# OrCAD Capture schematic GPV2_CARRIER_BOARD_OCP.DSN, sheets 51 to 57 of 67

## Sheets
51 057 CPLD 1: size C
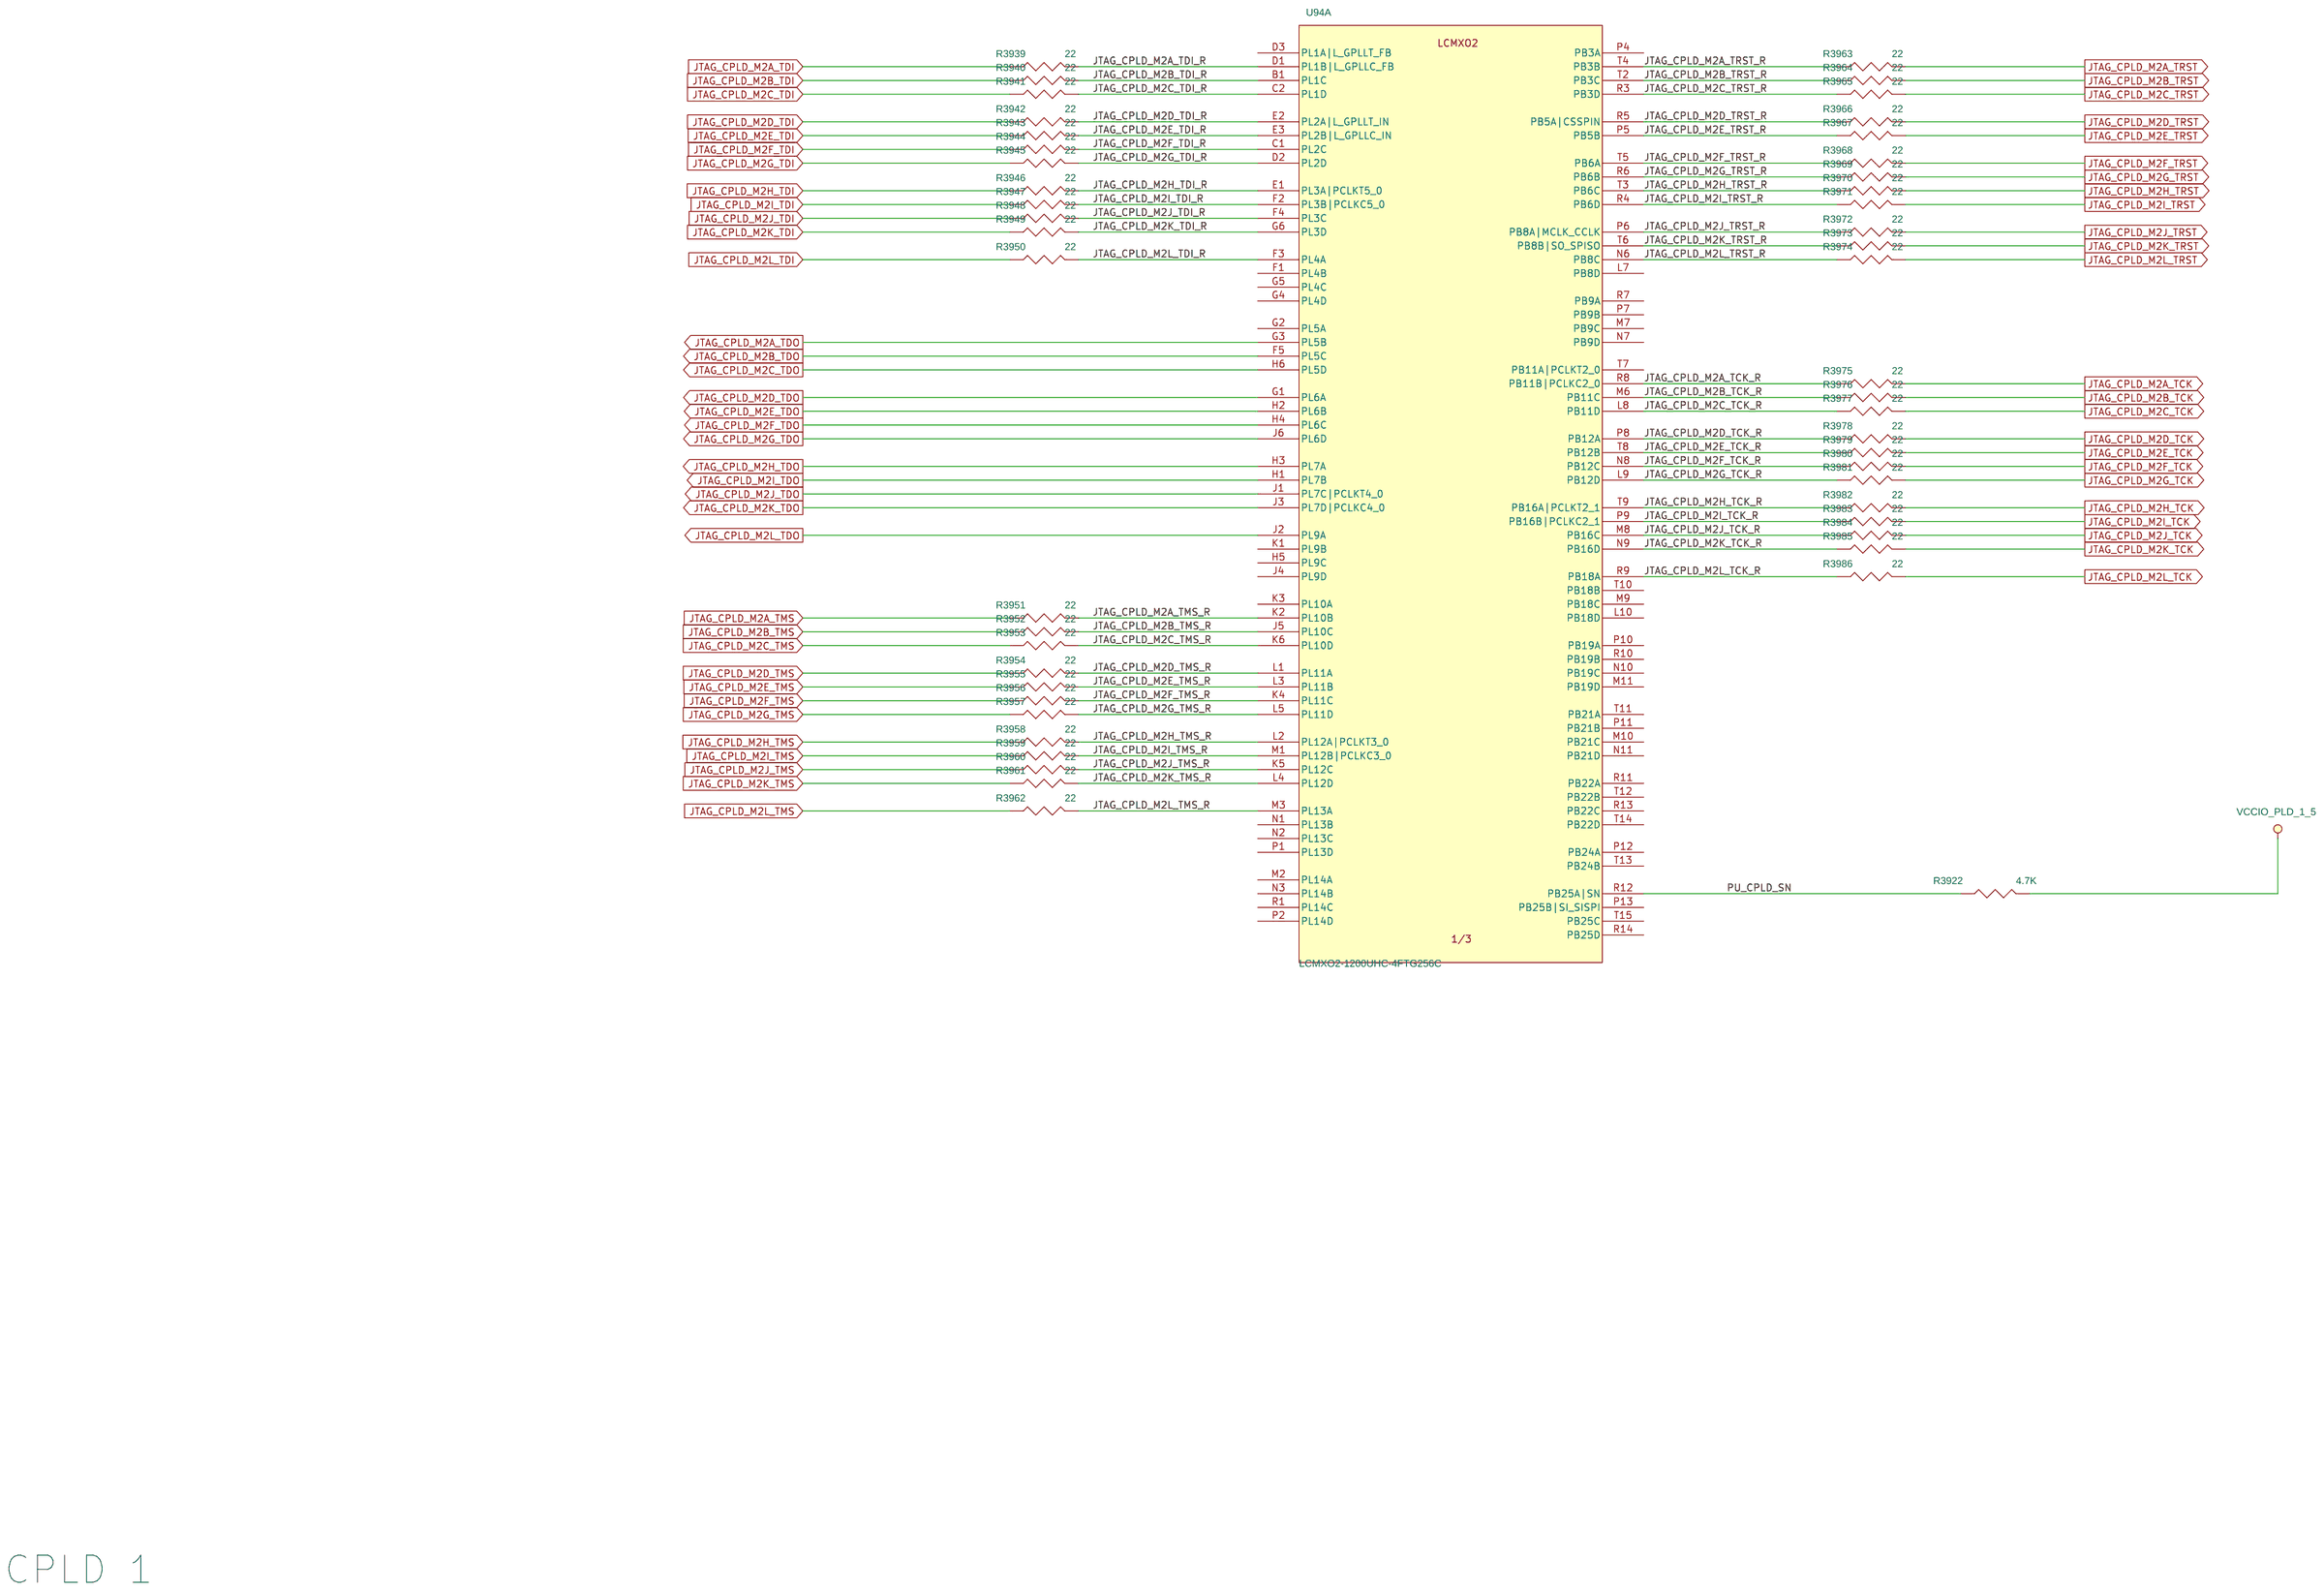
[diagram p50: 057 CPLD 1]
52 058 CPLD 2: size C
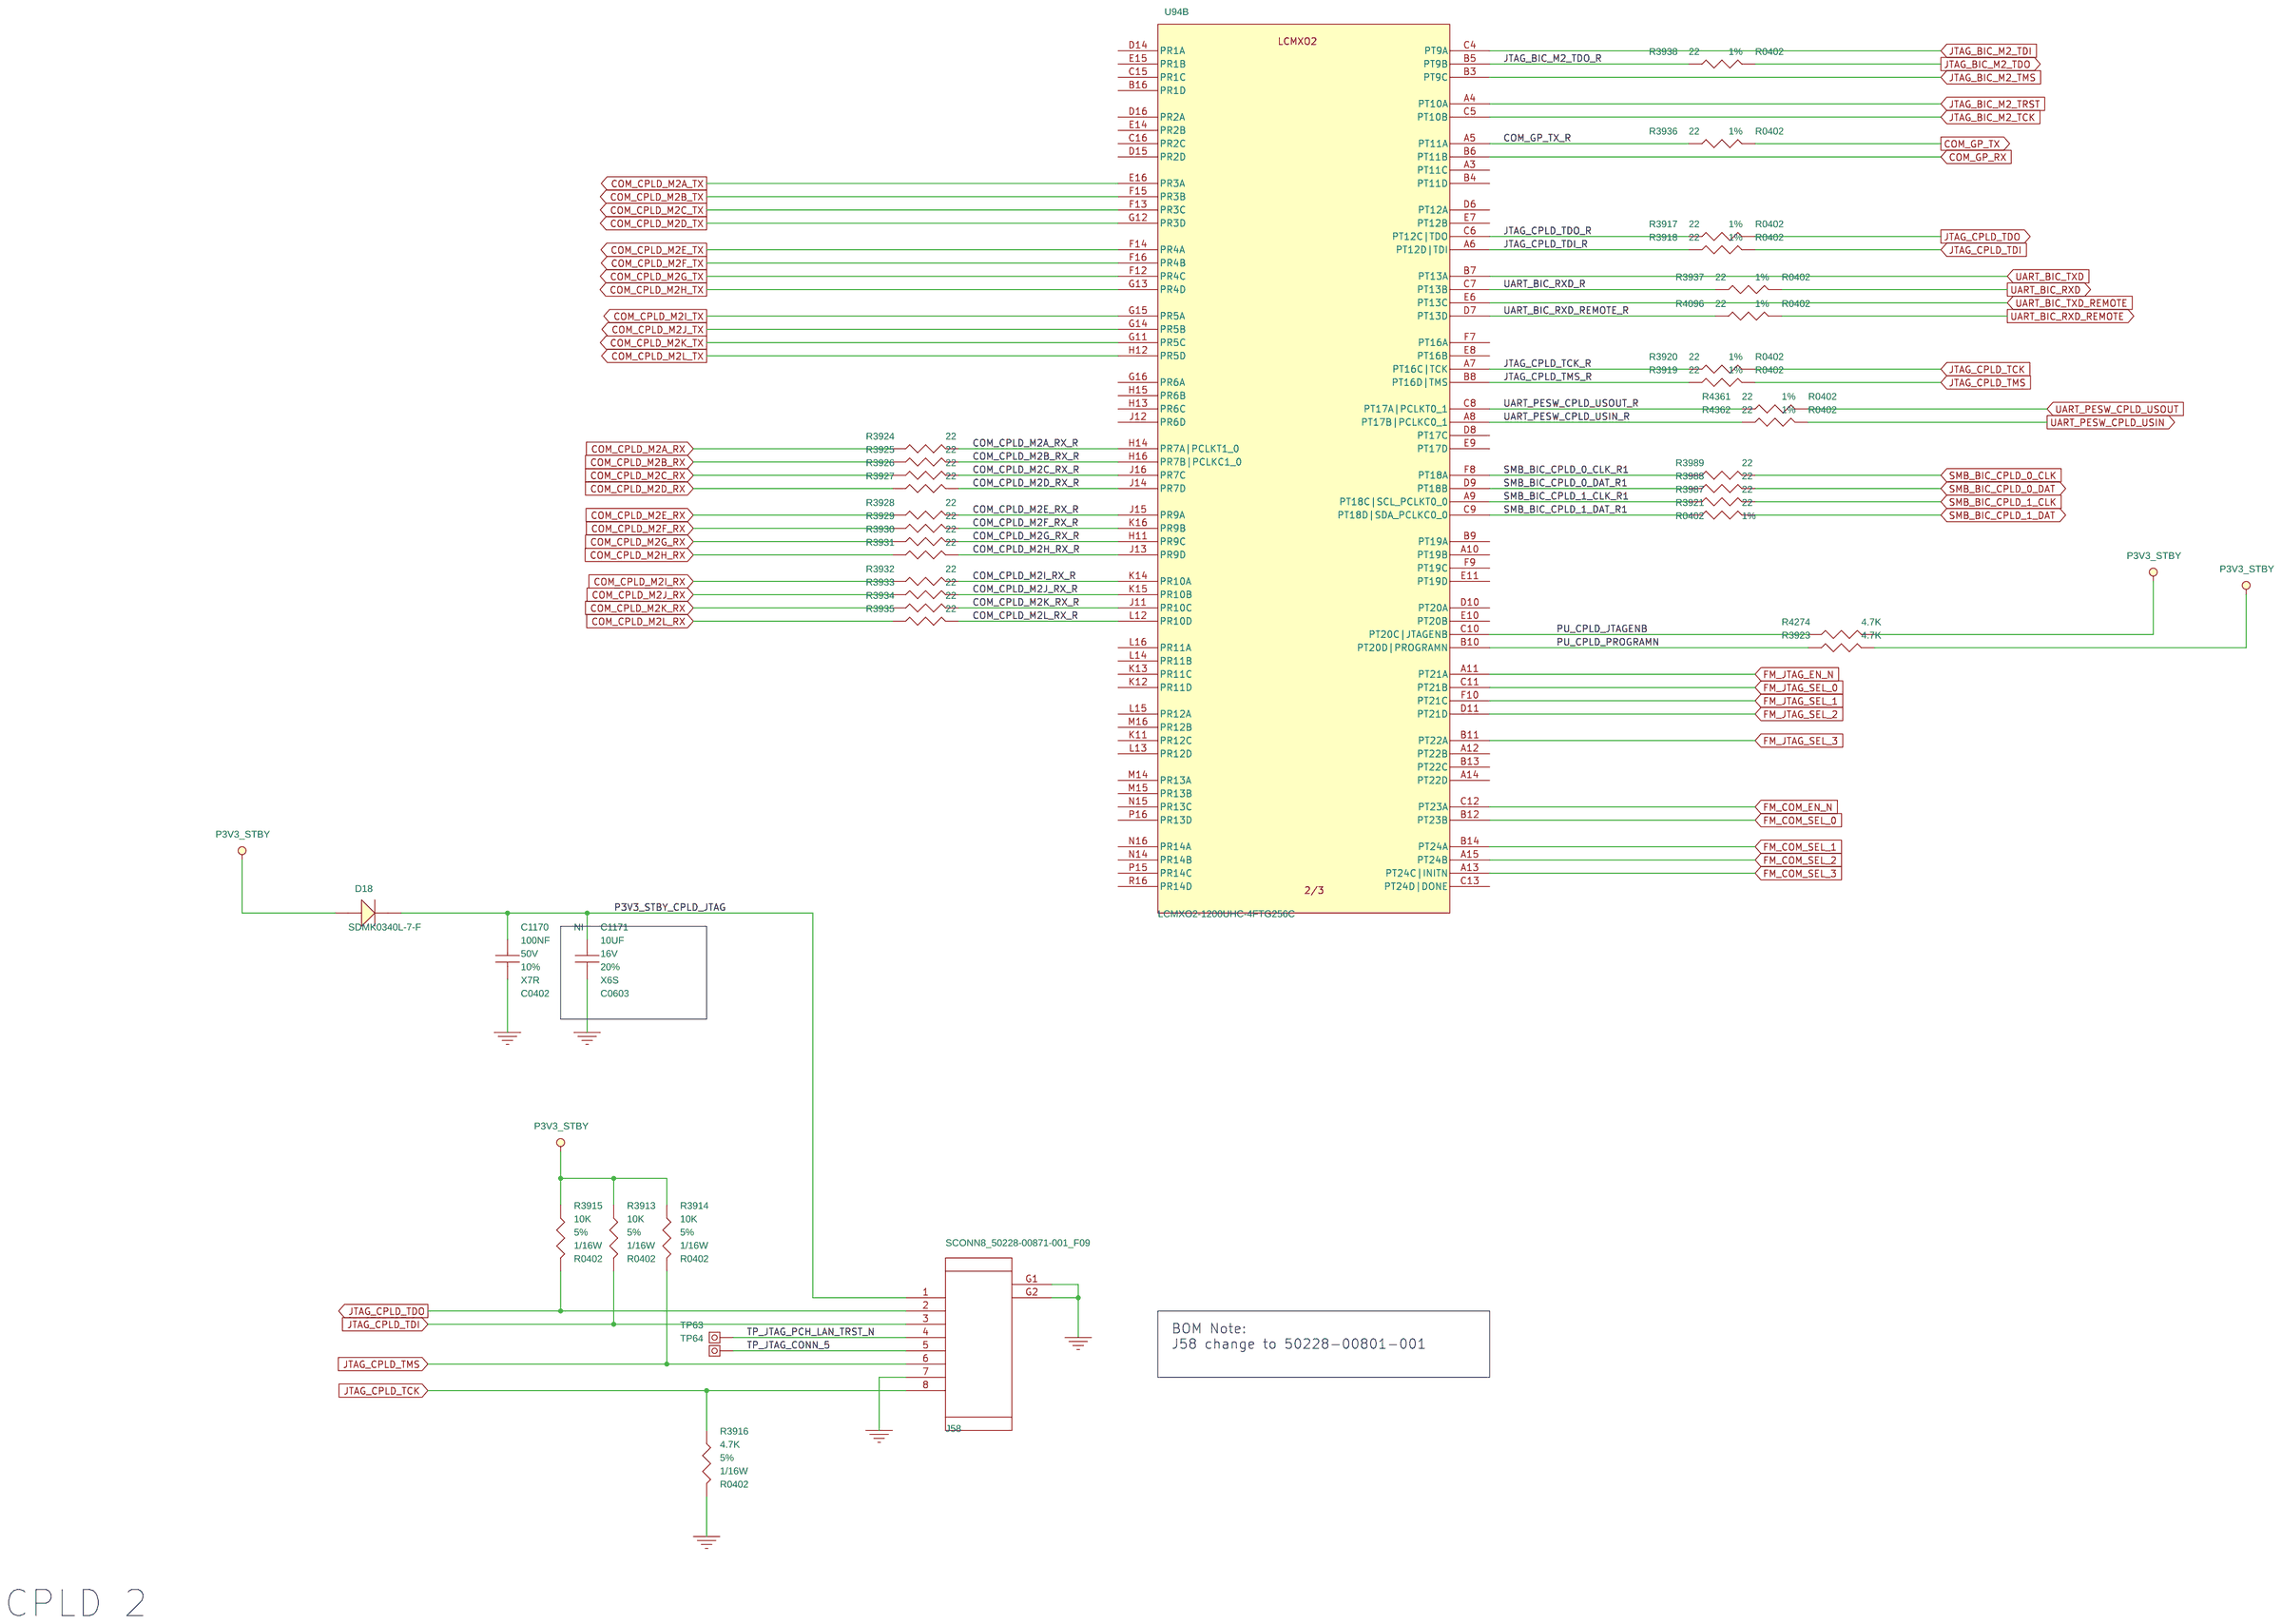
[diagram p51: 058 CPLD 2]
53 059 CPLD 3: size C
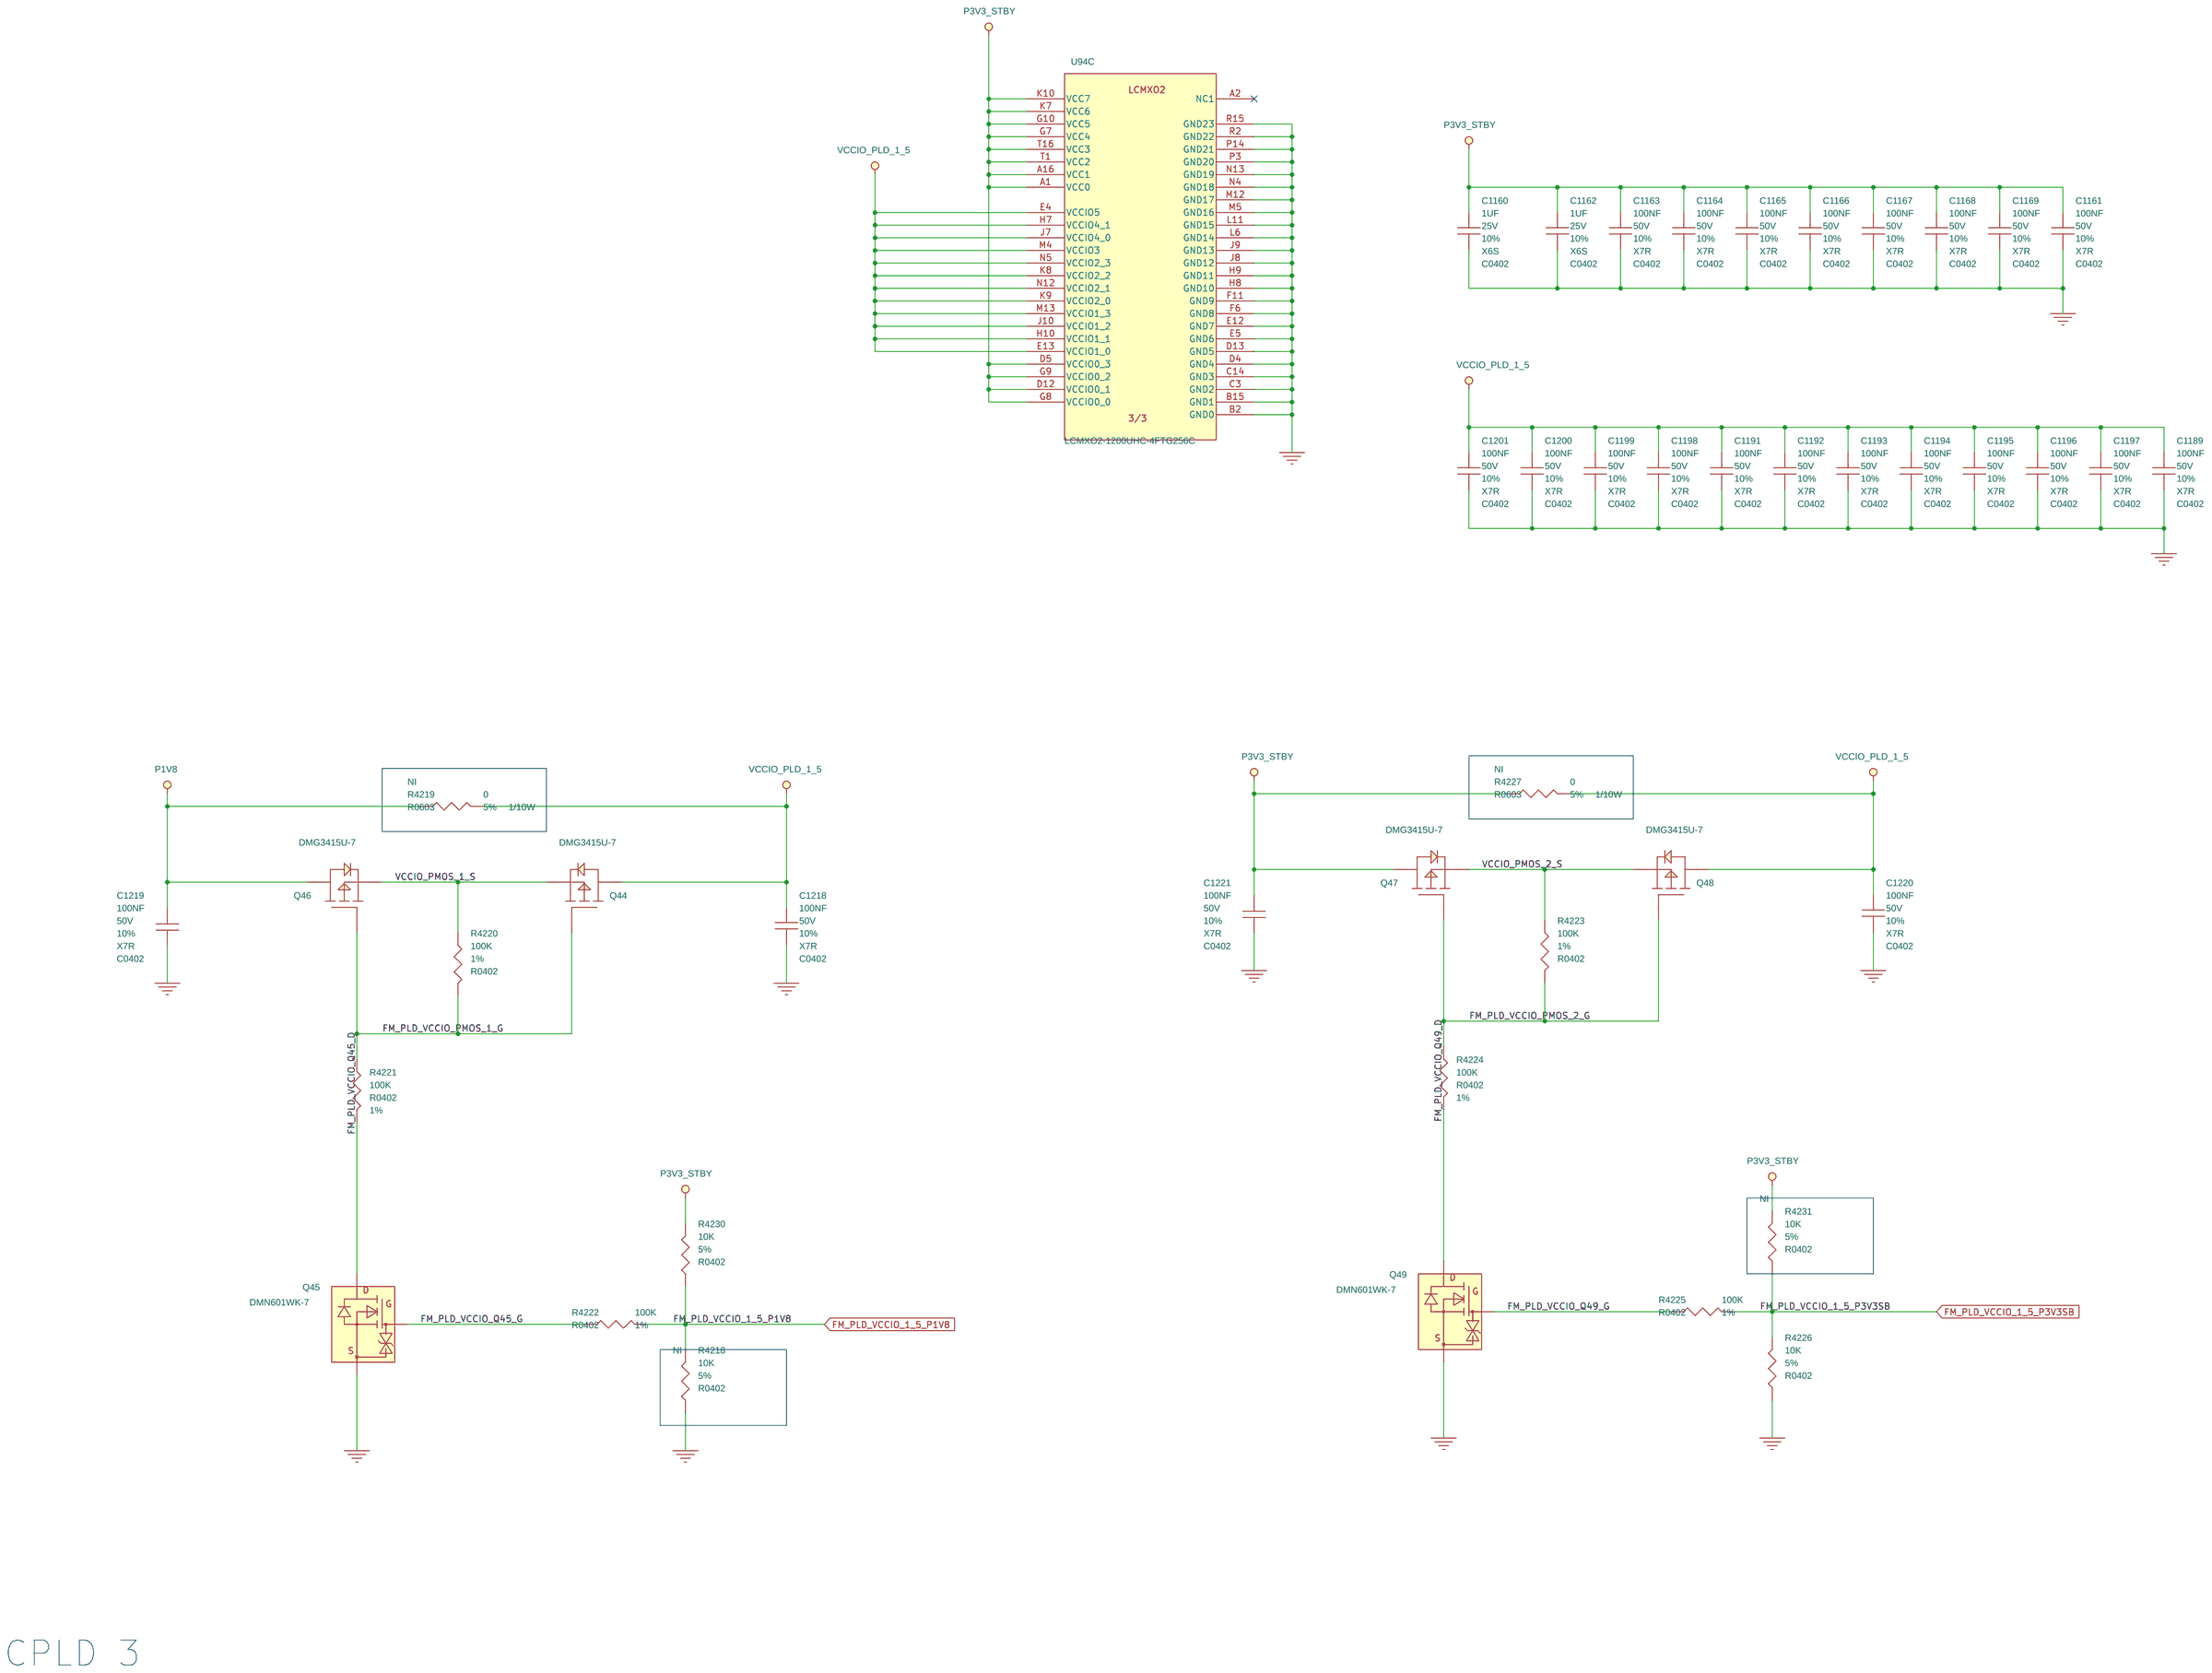
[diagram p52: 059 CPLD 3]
54 060 MISC 1: size C
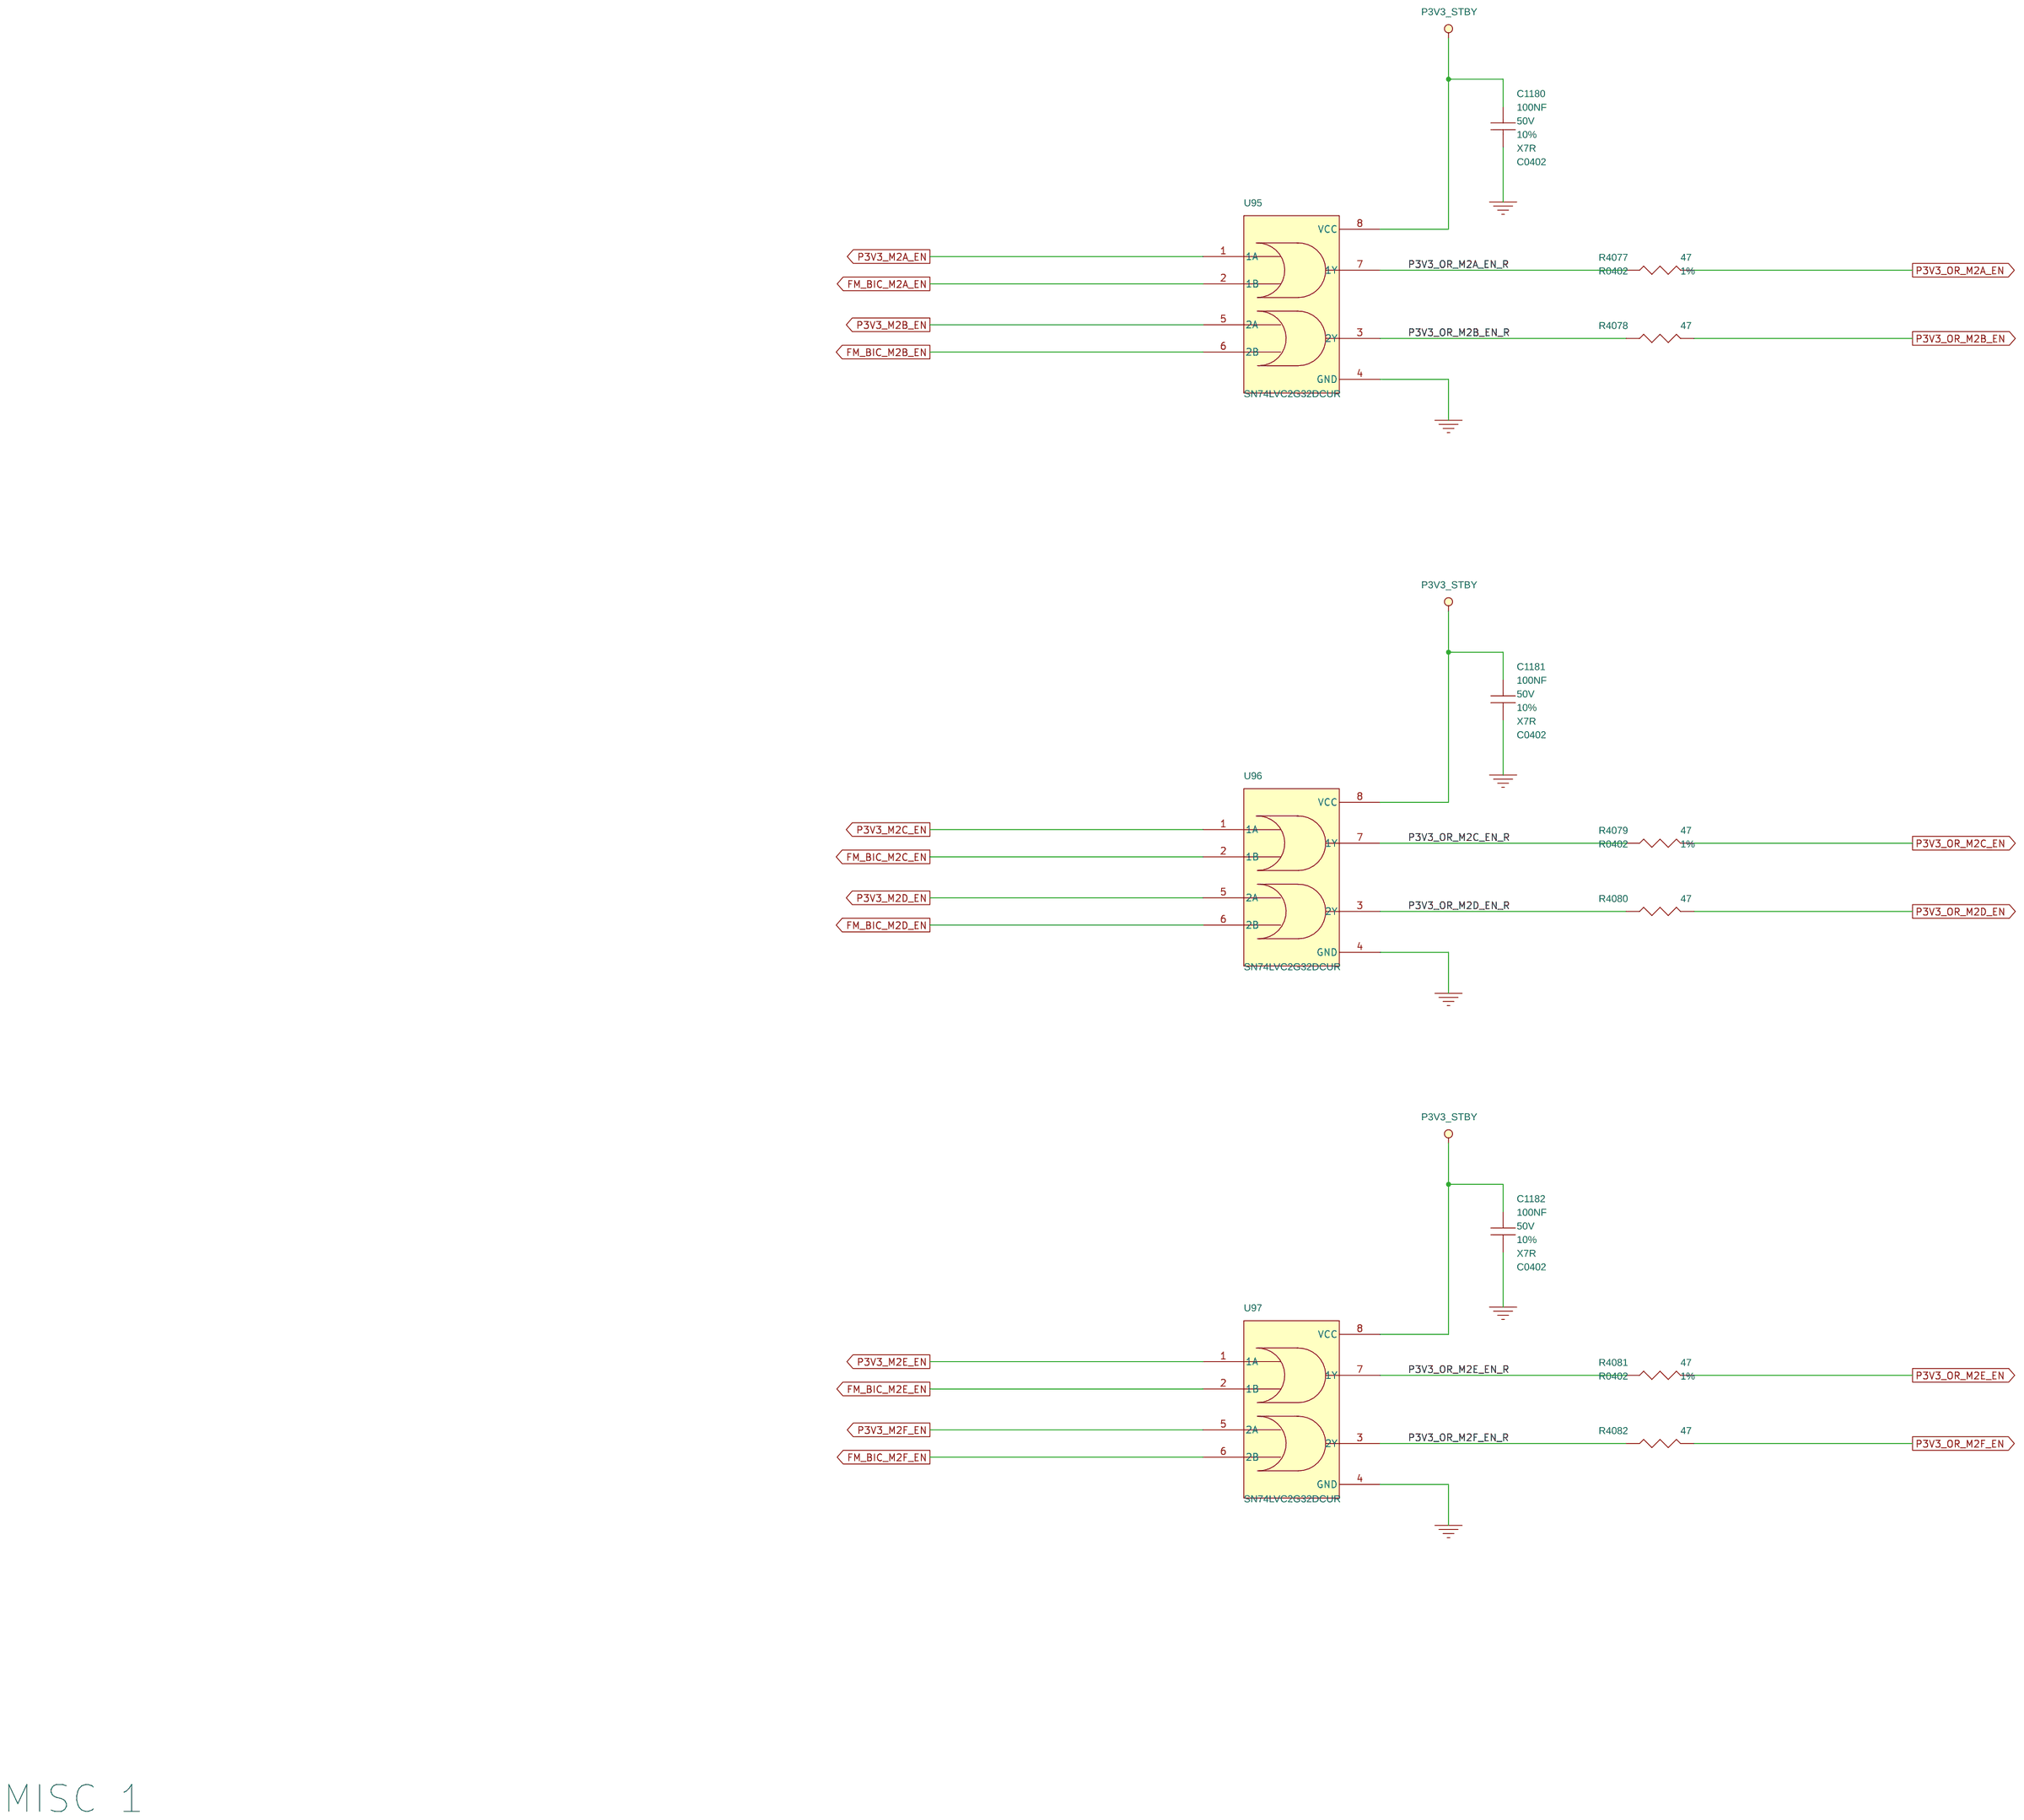
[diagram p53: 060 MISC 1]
55 061 MISC 2: size C
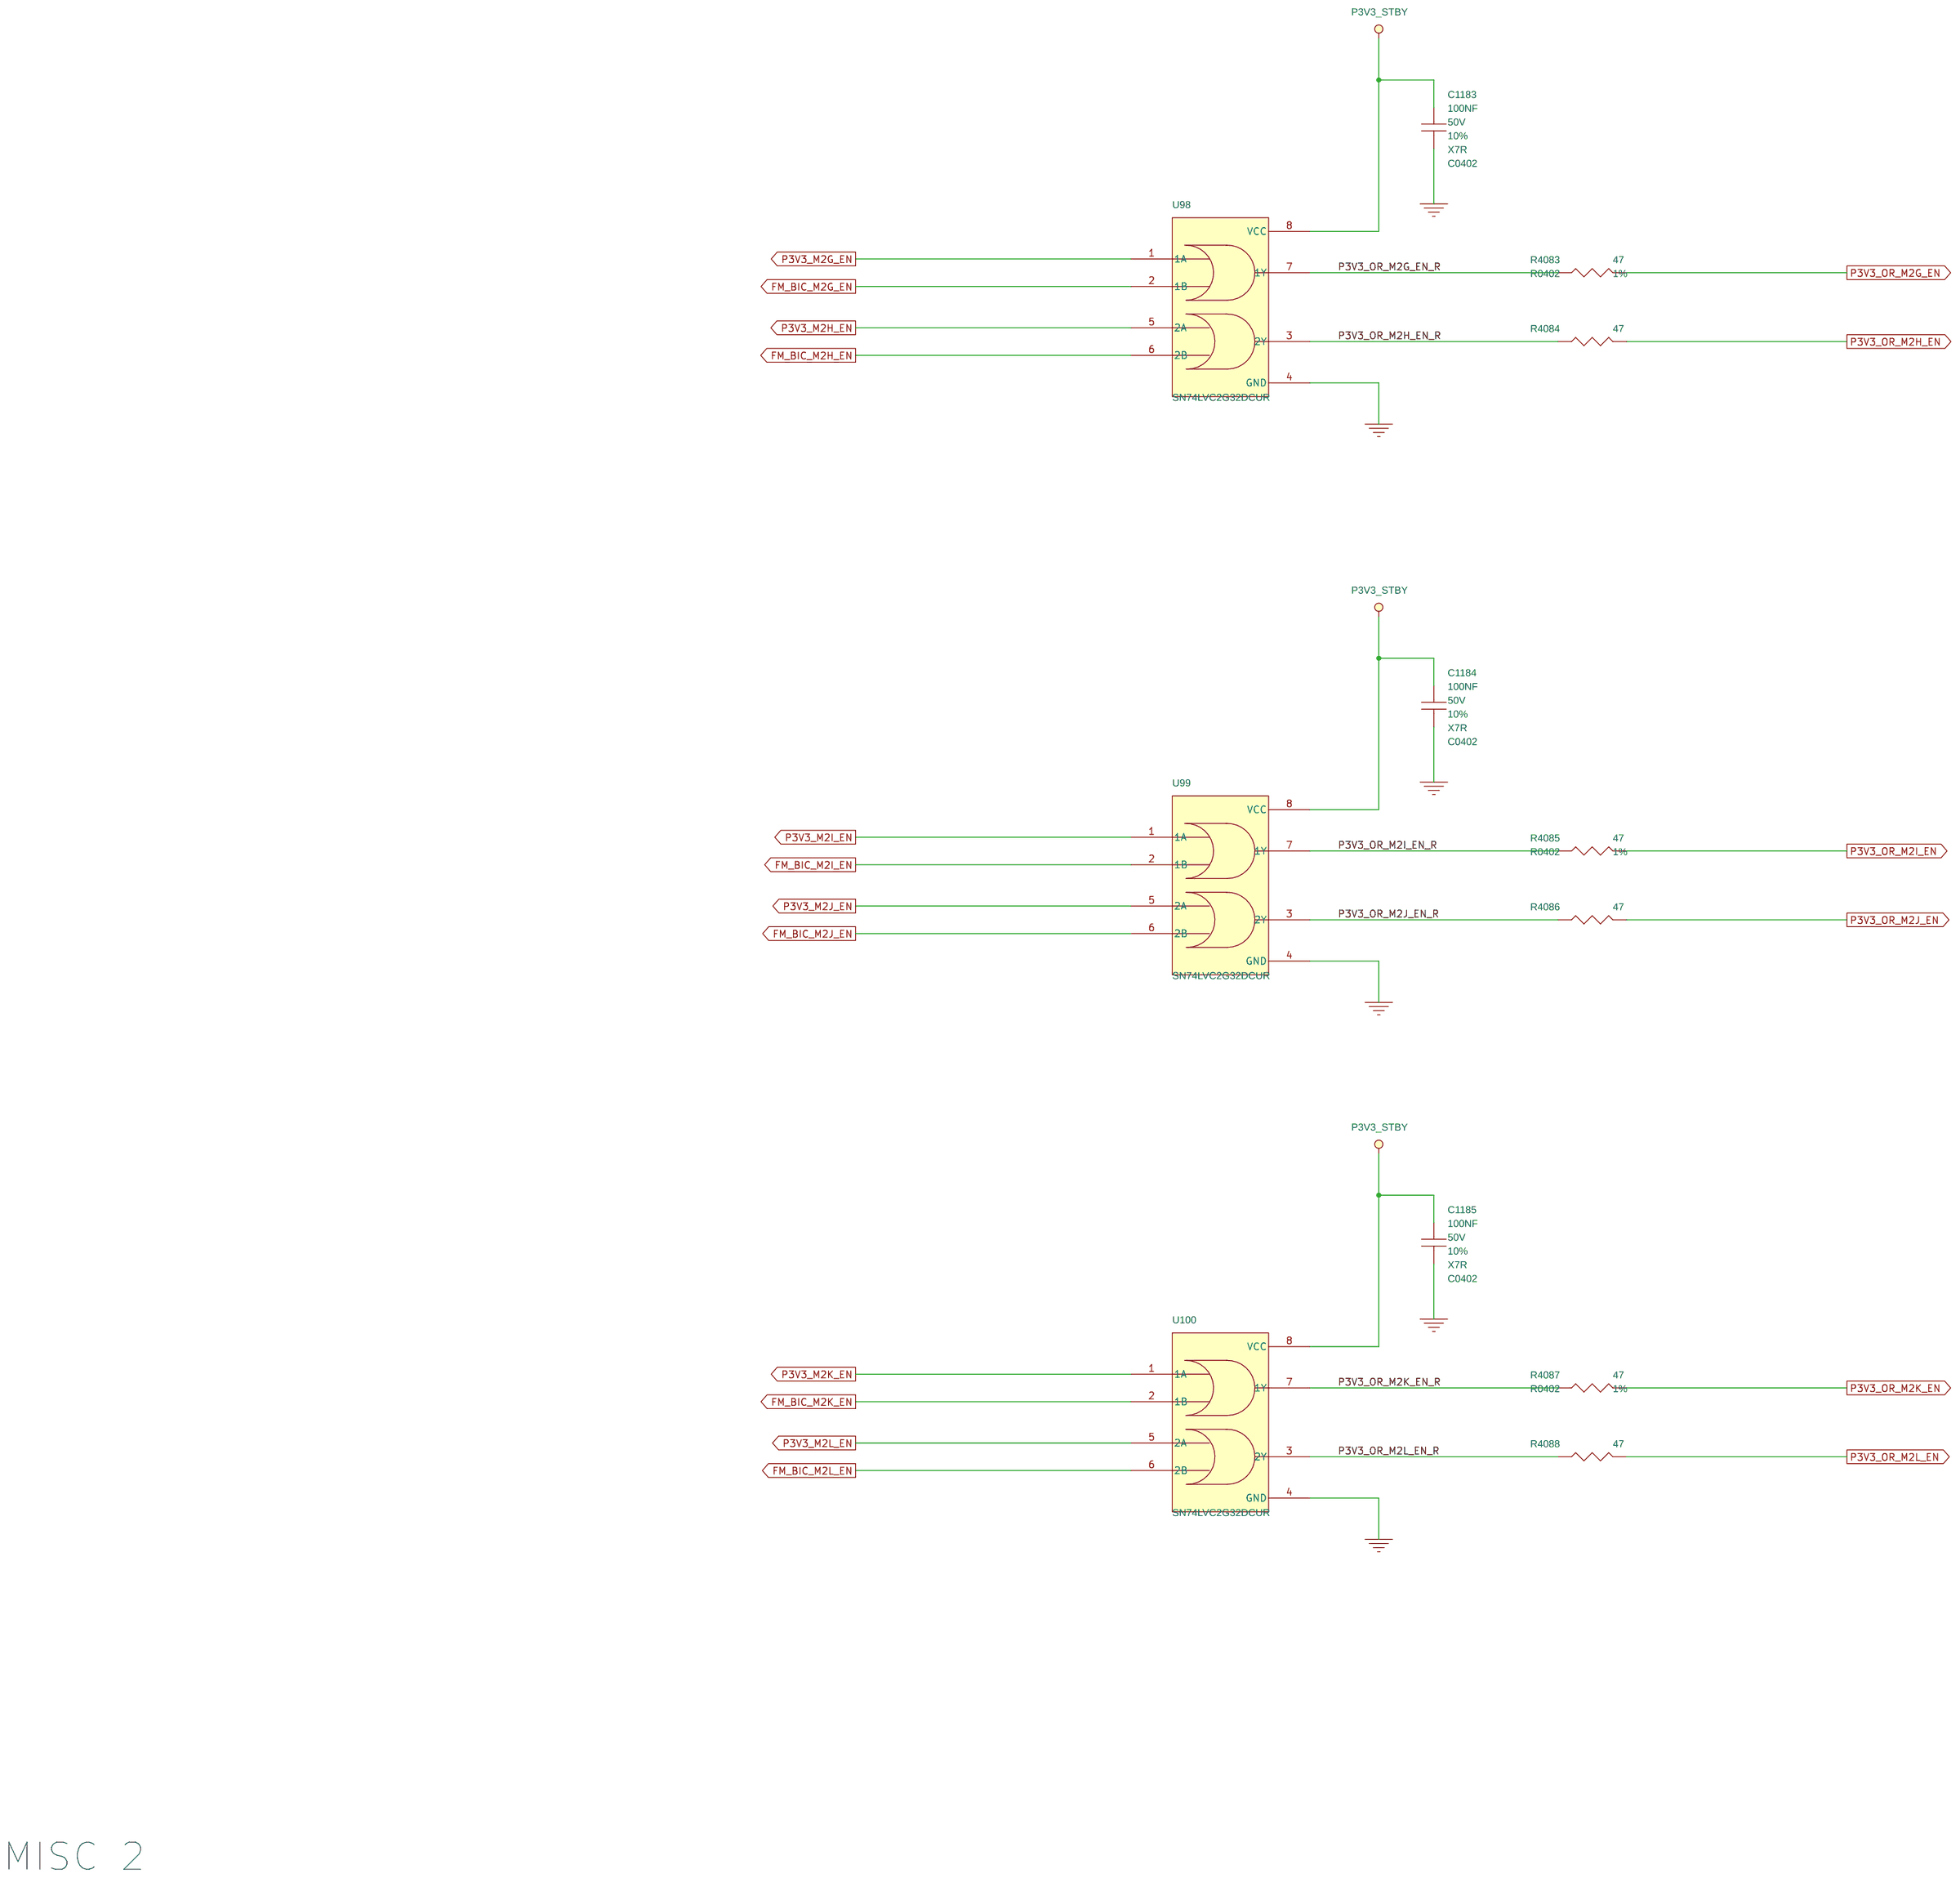
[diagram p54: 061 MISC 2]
56 062 P3V3_STBY: size C
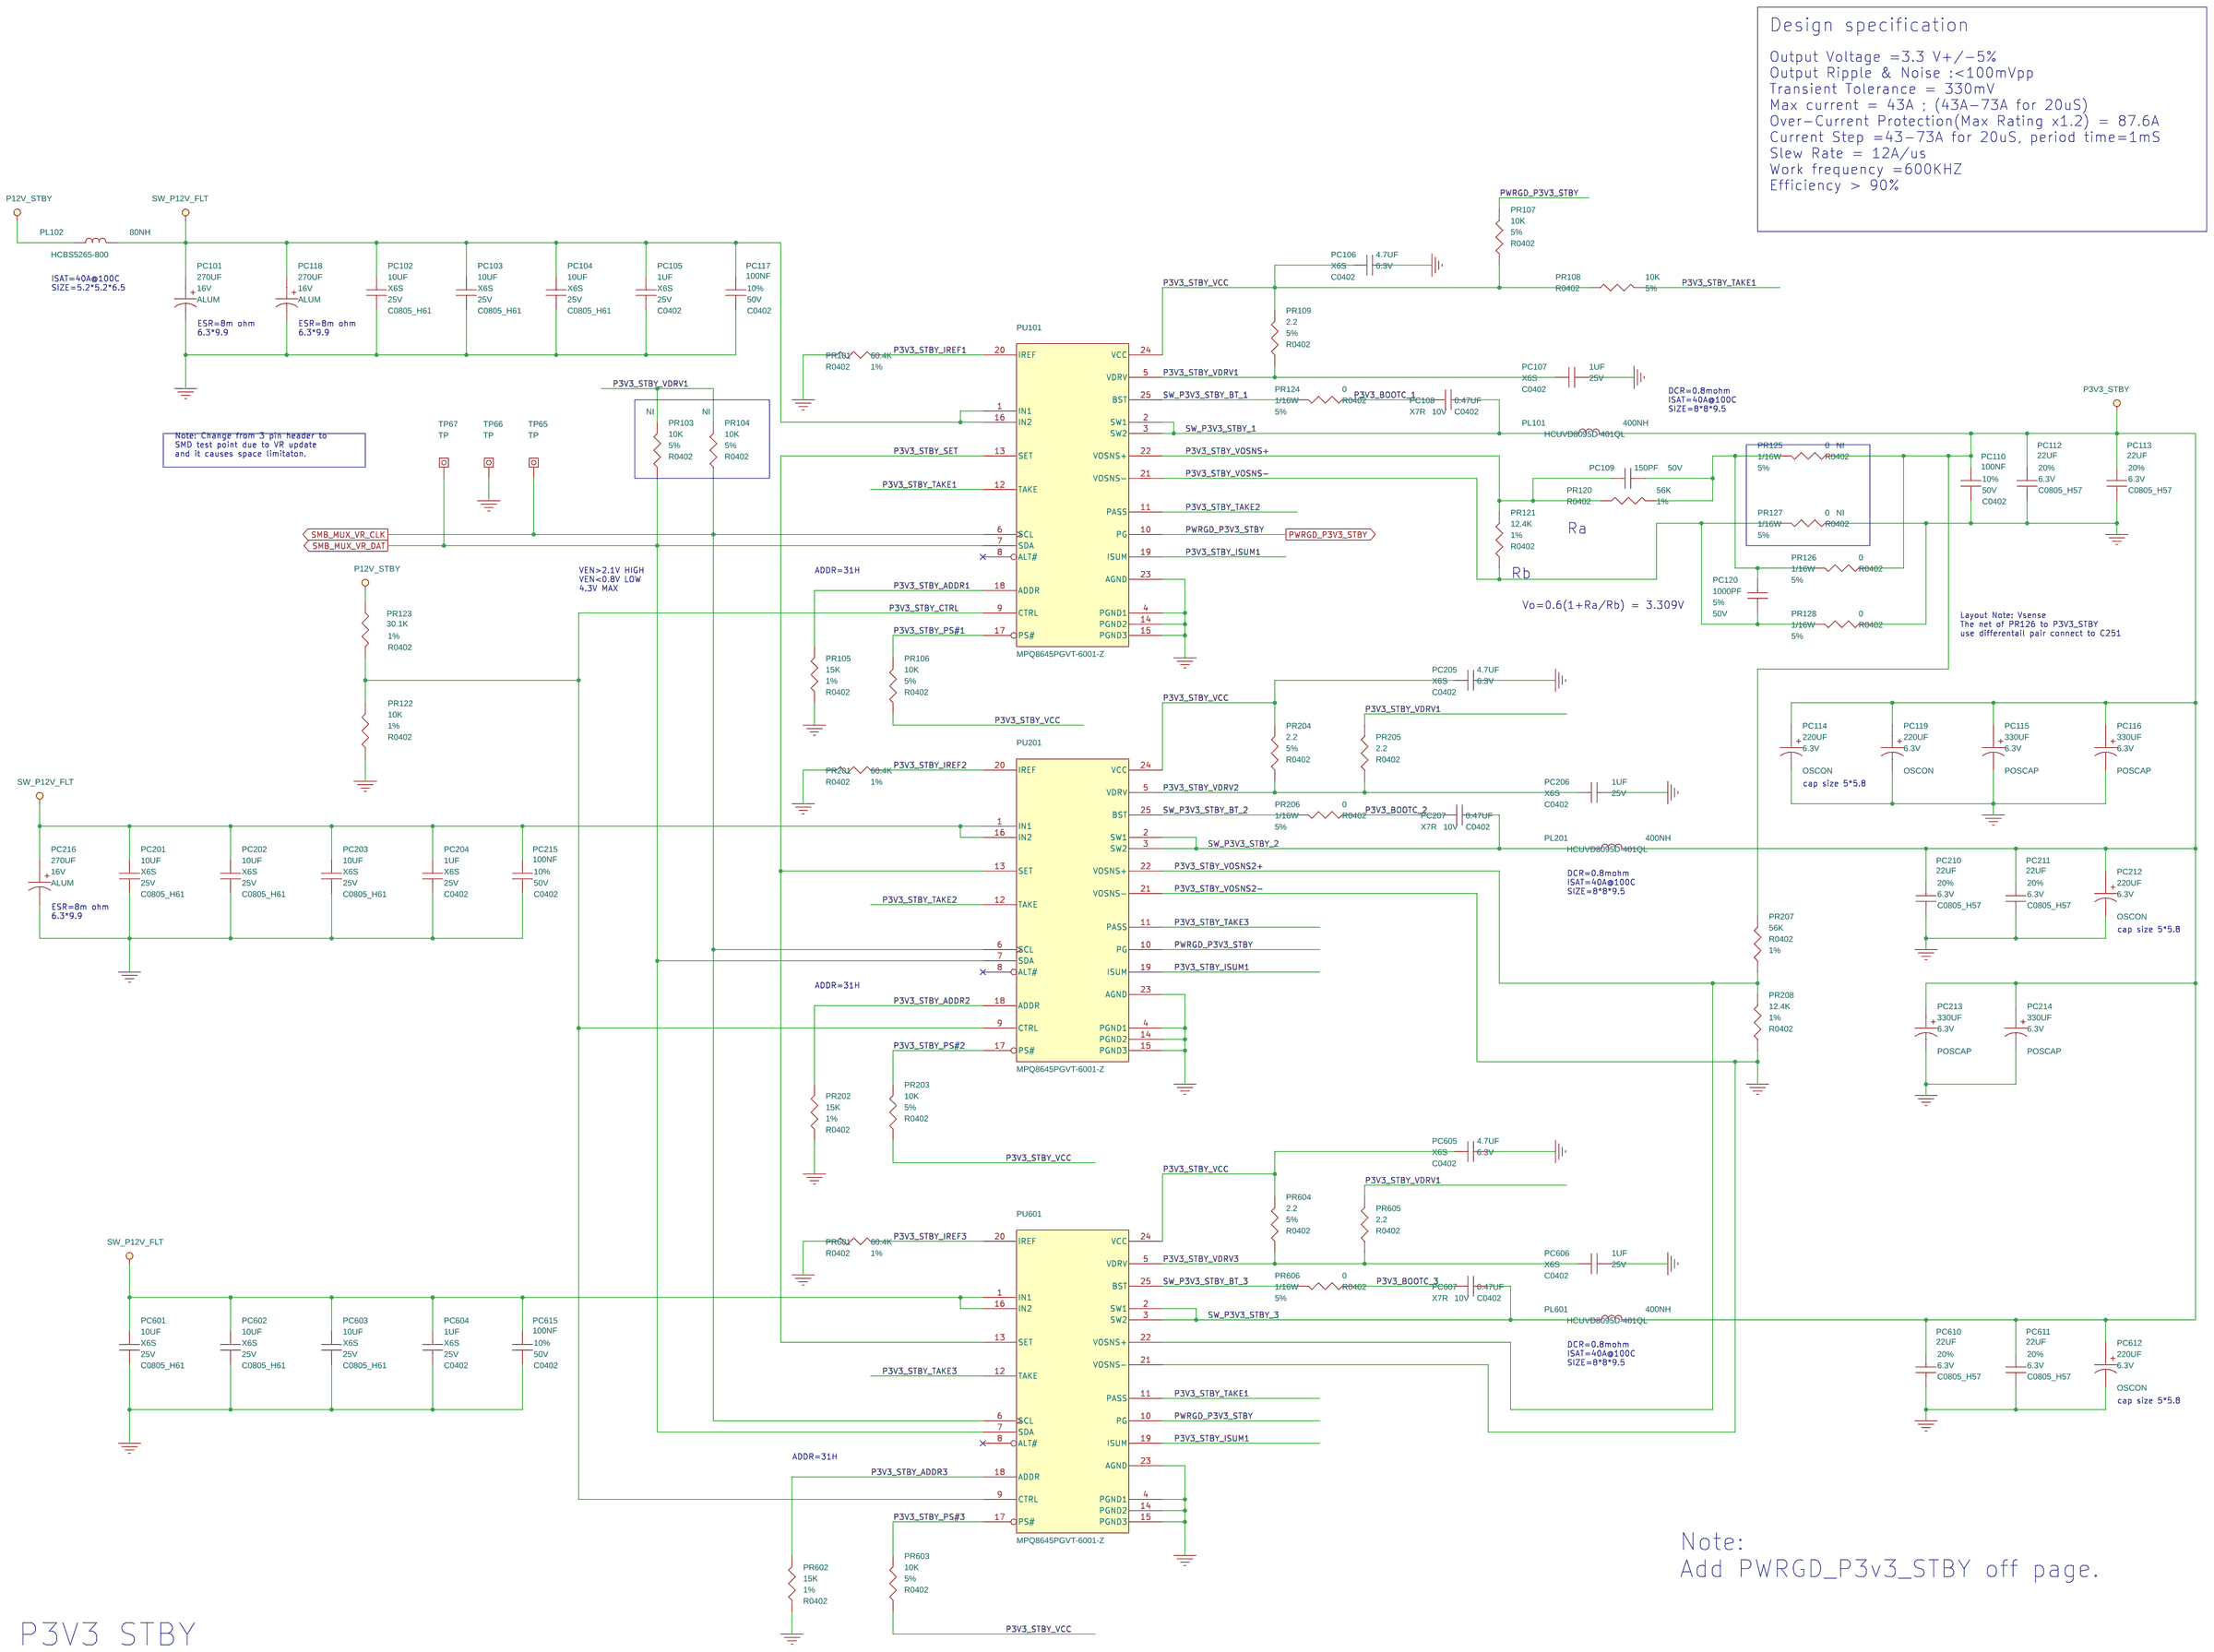
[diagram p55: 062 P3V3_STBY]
57 063 P0V92: size C
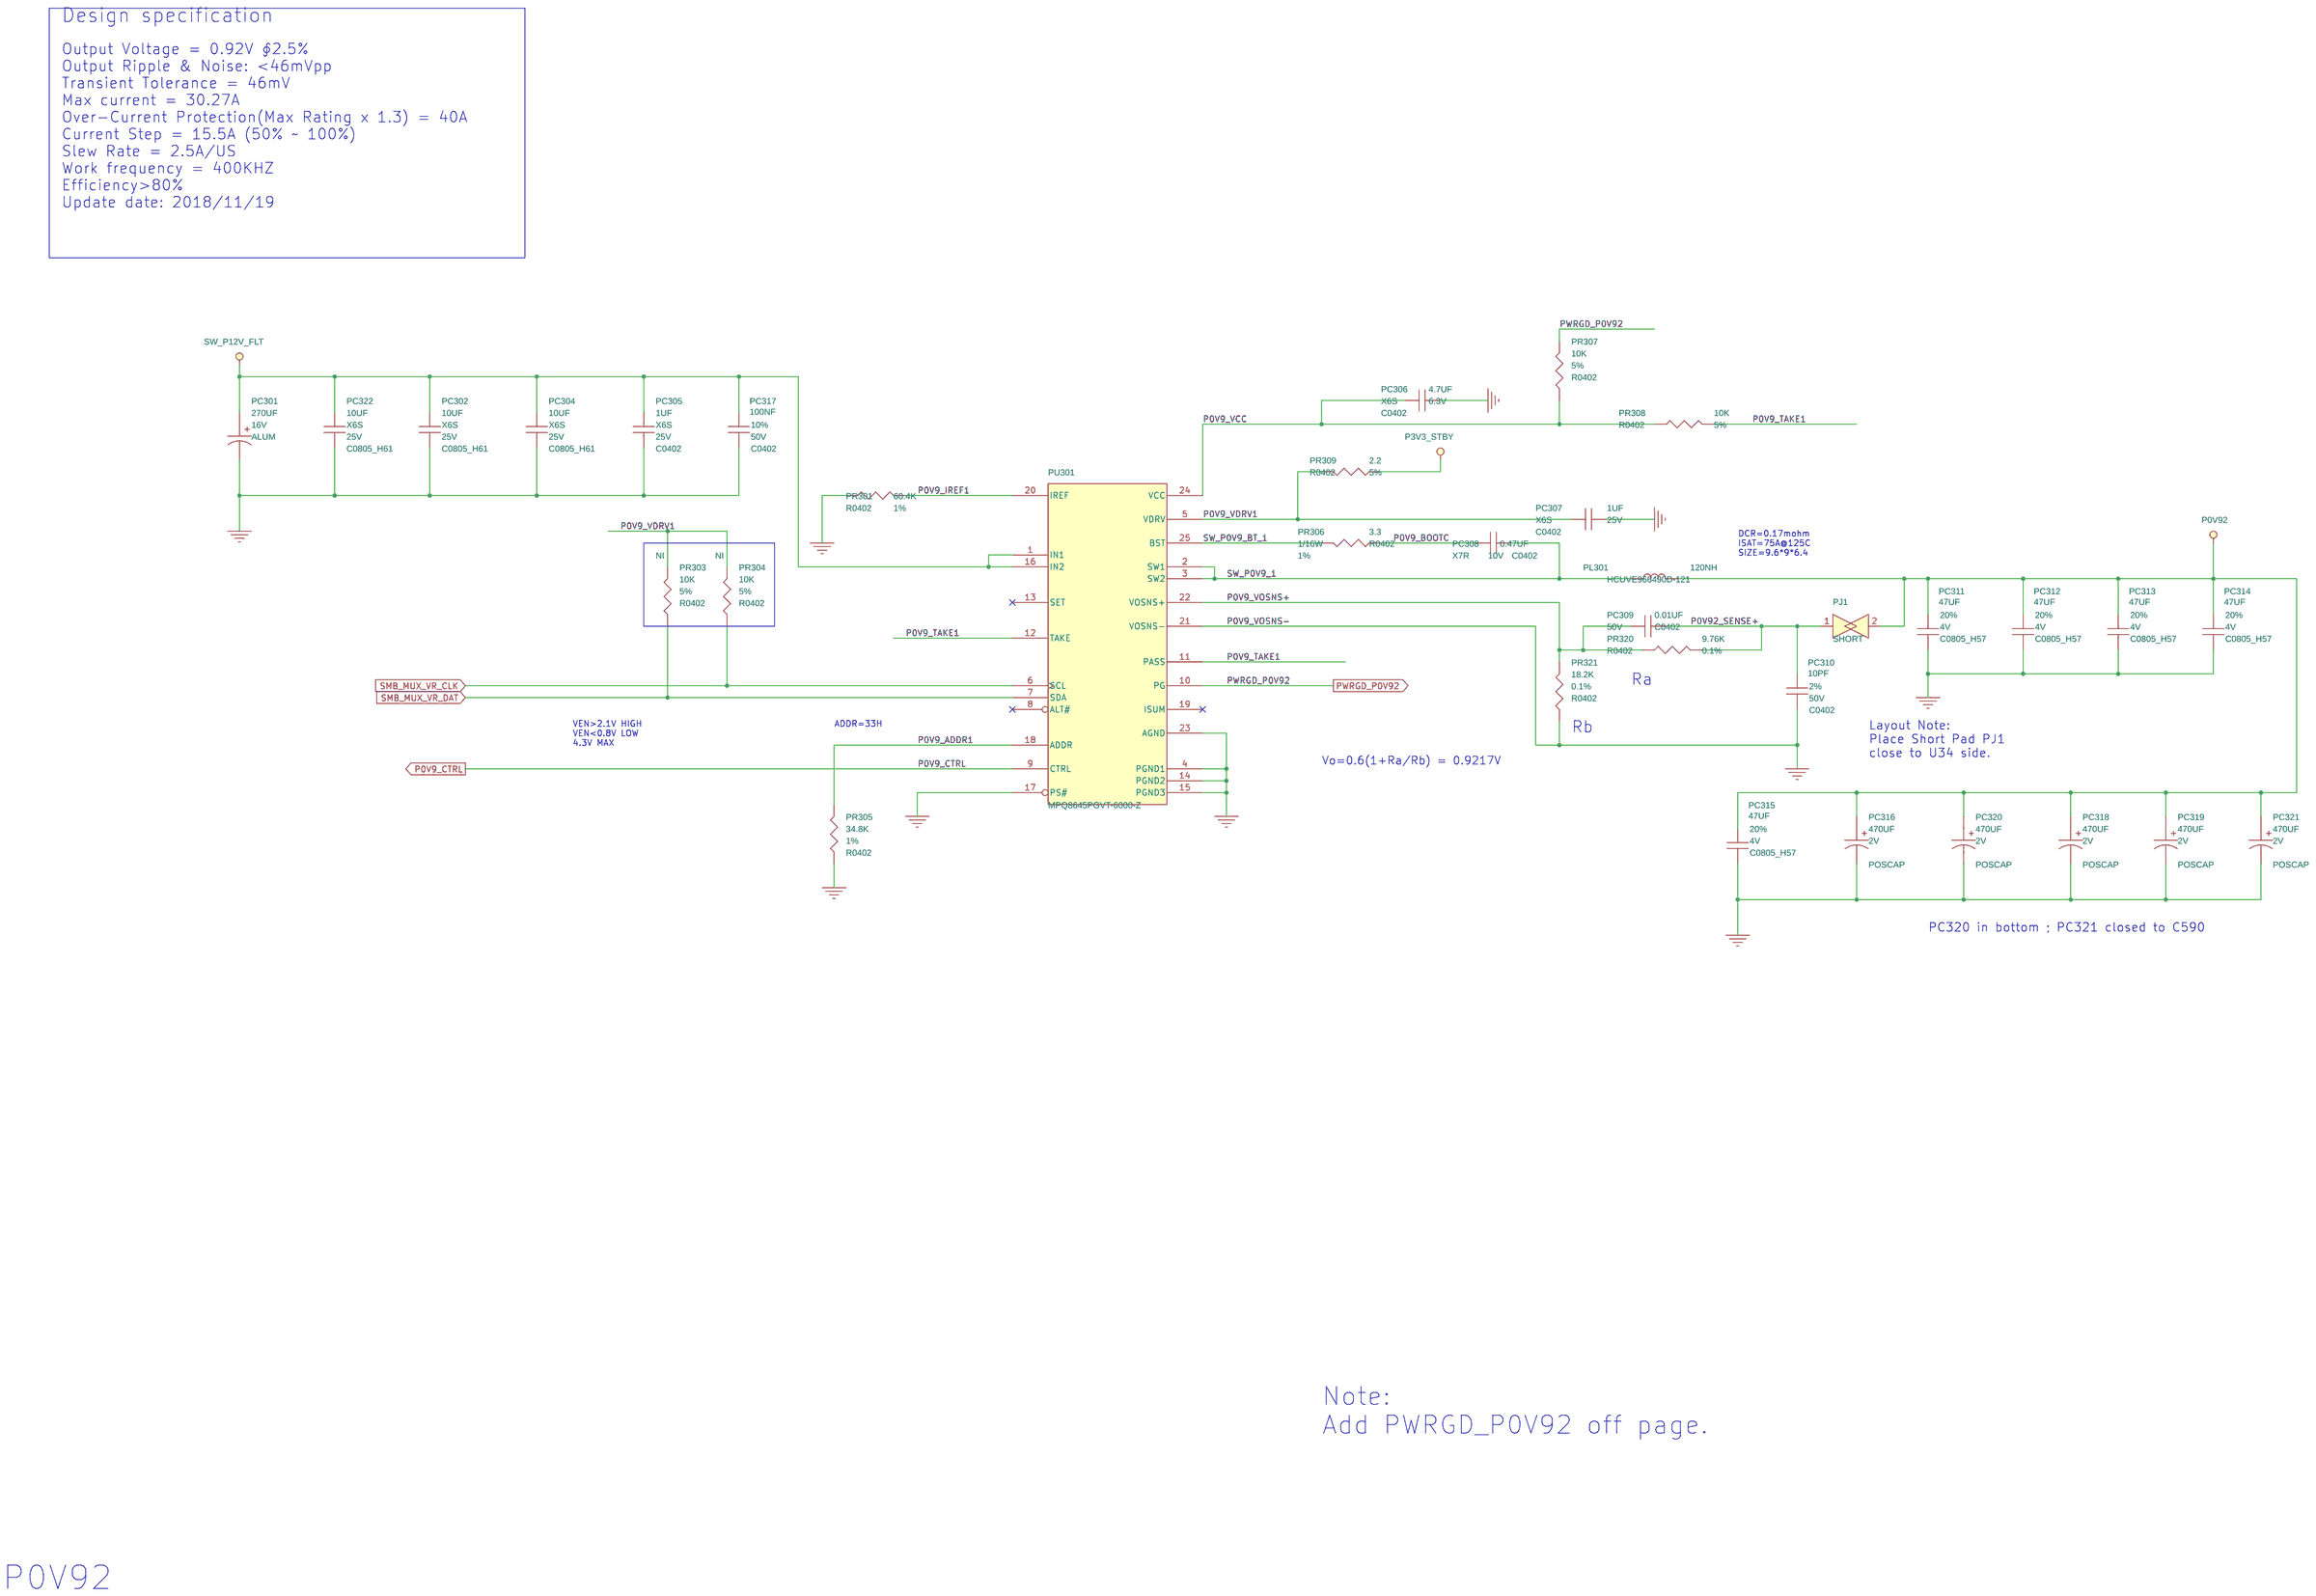
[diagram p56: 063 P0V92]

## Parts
sheet 057 CPLD 1
R3922  4.7K  [R0402]
R3939  22  [R0402]
R3940  22  [R0402]
R3941  22  [R0402]
R3942  22  [R0402]
R3943  22  [R0402]
R3944  22  [R0402]
R3945  22  [R0402]
R3946  22  [R0402]
R3947  22  [R0402]
R3948  22  [R0402]
R3949  22  [R0402]
R3950  22  [R0402]
R3951  22  [R0402]
R3952  22  [R0402]
R3953  22  [R0402]
R3954  22  [R0402]
R3955  22  [R0402]
R3956  22  [R0402]
R3957  22  [R0402]
R3958  22  [R0402]
R3959  22  [R0402]
R3960  22  [R0402]
R3961  22  [R0402]
R3962  22  [R0402]
R3963  22  [R0402]
R3964  22  [R0402]
R3965  22  [R0402]
R3966  22  [R0402]
R3967  22  [R0402]
R3968  22  [R0402]
R3969  22  [R0402]
R3970  22  [R0402]
R3971  22  [R0402]
R3972  22  [R0402]
R3973  22  [R0402]
R3974  22  [R0402]
R3975  22  [R0402]
R3976  22  [R0402]
R3977  22  [R0402]
R3978  22  [R0402]
R3979  22  [R0402]
R3980  22  [R0402]
R3981  22  [R0402]
R3982  22  [R0402]
R3983  22  [R0402]
R3984  22  [R0402]
R3985  22  [R0402]
R3986  22  [R0402]
sheet 058 CPLD 2
C1170  100NF  [C0402]
C1171  10UF  [C0603]
D18  SDMK0340L-7-F  [SOD323]
J58  SCONN8_50228-00871-001_F09  [CON_8S1H2S_P1XD_CAP_F09]
R3913  10K  [R0402]
R3914  10K  [R0402]
R3915  10K  [R0402]
R3916  4.7K  [R0402]
R3917  22  [R0402]
R3918  22  [R0402]
R3919  22  [R0402]
R3920  22  [R0402]
R3921  22  [R0402]
R3923  4.7K  [R0402]
R3924  22  [R0402]
R3925  22  [R0402]
R3926  22  [R0402]
R3927  22  [R0402]
R3928  22  [R0402]
R3929  22  [R0402]
R3930  22  [R0402]
R3931  22  [R0402]
R3932  22  [R0402]
R3933  22  [R0402]
R3934  22  [R0402]
R3935  22  [R0402]
R3936  22  [R0402]
R3937  22  [R0402]
R3938  22  [R0402]
R3987  22  [R0402]
R3988  22  [R0402]
R3989  22  [R0402]
R4096  22  [R0402]
R4274  4.7K  [R0402]
R4361  22  [R0402]
R4362  22  [R0402]
TP63  TP  [TP26D10]
TP64  TP  [TP26D10]
U94  LCMXO2-1200UHC-4FTG256C  [BGA256D]  (sections A,B,C)
sheet 059 CPLD 3
C1160  1UF  [C0402]
C1161  100NF  [C0402]
C1162  1UF  [C0402]
C1163  100NF  [C0402]
C1164  100NF  [C0402]
C1165  100NF  [C0402]
C1166  100NF  [C0402]
C1167  100NF  [C0402]
C1168  100NF  [C0402]
C1169  100NF  [C0402]
C1189  100NF  [C0402]
C1191  100NF  [C0402]
C1192  100NF  [C0402]
C1193  100NF  [C0402]
C1194  100NF  [C0402]
C1195  100NF  [C0402]
C1196  100NF  [C0402]
C1197  100NF  [C0402]
C1198  100NF  [C0402]
C1199  100NF  [C0402]
C1200  100NF  [C0402]
C1201  100NF  [C0402]
C1218  100NF  [C0402]
C1219  100NF  [C0402]
C1220  100NF  [C0402]
C1221  100NF  [C0402]
Q44  DMG3415U-7  [SOT23_GDSXC]
Q45  DMN601WK-7  [SOT323_GDS_2-15X1-3]
Q46  DMG3415U-7  [SOT23_GDSXC]
Q47  DMG3415U-7  [SOT23_GDSXC]
Q48  DMG3415U-7  [SOT23_GDSXC]
Q49  DMN601WK-7  [SOT323_GDS_2-15X1-3]
R4218  10K  [R0402]
R4219  0  [R0603]
R4220  100K  [R0402]
R4221  100K  [R0402]
R4222  100K  [R0402]
R4223  100K  [R0402]
R4224  100K  [R0402]
R4225  100K  [R0402]
R4226  10K  [R0402]
R4227  0  [R0603]
R4230  10K  [R0402]
R4231  10K  [R0402]
sheet 060 MISC 1
C1180  100NF  [C0402]
C1181  100NF  [C0402]
C1182  100NF  [C0402]
R4077  47  [R0402]
R4078  47  [R0402]
R4079  47  [R0402]
R4080  47  [R0402]
R4081  47  [R0402]
R4082  47  [R0402]
U95  SN74LVC2G32DCUR  [SOP8]
U96  SN74LVC2G32DCUR  [SOP8]
U97  SN74LVC2G32DCUR  [SOP8]
sheet 061 MISC 2
C1183  100NF  [C0402]
C1184  100NF  [C0402]
C1185  100NF  [C0402]
R4083  47  [R0402]
R4084  47  [R0402]
R4085  47  [R0402]
R4086  47  [R0402]
R4087  47  [R0402]
R4088  47  [R0402]
U98  SN74LVC2G32DCUR  [SOP8]
U99  SN74LVC2G32DCUR  [SOP8]
U100  SN74LVC2G32DCUR  [SOP8]
sheet 062 P3V3_STBY
PC101  270UF  [EC83_248_390S]
PC102  10UF  [C0805_H61]
PC103  10UF  [C0805_H61]
PC104  10UF  [C0805_H61]
PC105  1UF  [C0402]
PC106  4.7UF  [C0402]
PC107  1UF  [C0402]
PC108  0.47UF  [C0402]
PC109  150PF  [C0402]
PC110  100NF  [C0402]
PC112  22UF  [C0805_H57]
PC113  22UF  [C0805_H57]
PC114  220UF  [EC56_197_229S]
PC115  330UF  [TAJ_D2E]
PC116  330UF  [TAJ_D2E]
PC117  100NF  [C0402]
PC118  270UF  [EC83_248_390S]
PC119  220UF  [EC56_197_229S]
PC120  1000PF  [C0402]
PC201  10UF  [C0805_H61]
PC202  10UF  [C0805_H61]
PC203  10UF  [C0805_H61]
PC204  1UF  [C0402]
PC205  4.7UF  [C0402]
PC206  1UF  [C0402]
PC207  0.47UF  [C0402]
PC210  22UF  [C0805_H57]
PC211  22UF  [C0805_H57]
PC212  220UF  [EC56_197_229S]
PC213  330UF  [TAJ_D2E]
PC214  330UF  [TAJ_D2E]
PC215  100NF  [C0402]
PC216  270UF  [EC83_248_390S]
PC601  10UF  [C0805_H61]
PC602  10UF  [C0805_H61]
PC603  10UF  [C0805_H61]
PC604  1UF  [C0402]
PC605  4.7UF  [C0402]
PC606  1UF  [C0402]
PC607  0.47UF  [C0402]
PC610  22UF  [C0805_H57]
PC611  22UF  [C0805_H57]
PC612  220UF  [EC56_197_229S]
PC615  100NF  [C0402]
PL101  400NH  [L_HCUVD8095D-102KBQL_8X8]
PL102  80NH  [L_HCBS5265_5-2X5-2]
PL201  400NH  [L_HCUVD8095D-102KBQL_8X8]
PL601  400NH  [L_HCUVD8095D-102KBQL_8X8]
PR101  60.4K  [R0402]
PR103  10K  [R0402]
PR104  10K  [R0402]
PR105  15K  [R0402]
PR106  10K  [R0402]
PR107  10K  [R0402]
PR108  10K  [R0402]
PR109  2.2  [R0402]
PR120  56K  [R0402]
PR121  12.4K  [R0402]
PR122  10K  [R0402]
PR123  30.1K  [R0402]
PR124  0  [R0402]
PR125  0  [R0402]
PR126  0  [R0402]
PR127  0  [R0402]
PR128  0  [R0402]
PR201  60.4K  [R0402]
PR202  15K  [R0402]
PR203  10K  [R0402]
PR204  2.2  [R0402]
PR205  2.2  [R0402]
PR206  0  [R0402]
PR207  56K  [R0402]
PR208  12.4K  [R0402]
PR601  60.4K  [R0402]
PR602  15K  [R0402]
PR603  10K  [R0402]
PR604  2.2  [R0402]
PR605  2.2  [R0402]
PR606  0  [R0402]
PU101  MPQ8645PGVT-6001-Z  [TQFN25_5X4]
PU201  MPQ8645PGVT-6001-Z  [TQFN25_5X4]
PU601  MPQ8645PGVT-6001-Z  [TQFN25_5X4]
TP65  TP  [TP30]
TP66  TP  [TP30]
TP67  TP  [TP30]
sheet 063 P0V92
PC301  270UF  [EC83_248_390S]
PC302  10UF  [C0805_H61]
PC304  10UF  [C0805_H61]
PC305  1UF  [C0402]
PC306  4.7UF  [C0402]
PC307  1UF  [C0402]
PC308  0.47UF  [C0402]
PC309  0.01UF  [C0402]
PC310  10PF  [C0402]
PC311  47UF  [C0805_H57]
PC312  47UF  [C0805_H57]
PC313  47UF  [C0805_H57]
PC314  47UF  [C0805_H57]
PC315  47UF  [C0805_H57]
PC316  470UF  [TAJ_DXC]
PC317  100NF  [C0402]
PC318  470UF  [TAJ_DXC]
PC319  470UF  [TAJ_DXC]
PC320  470UF  [TAJ_DXC]
PC321  470UF  [TAJ_DXC]
PC322  10UF  [C0805_H61]
PJ1  SHORT  [SHORT_R0603]
PL301  120NH  [L_HCUVE966490D-121]
PR301  60.4K  [R0402]
PR303  10K  [R0402]
PR304  10K  [R0402]
PR305  34.8K  [R0402]
PR306  3.3  [R0402]
PR307  10K  [R0402]
PR308  10K  [R0402]
PR309  2.2  [R0402]
PR320  9.76K  [R0402]
PR321  18.2K  [R0402]
PU301  MPQ8645PGVT-6000-Z  [TQFN25_5X4]

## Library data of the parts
R3916 R3922 R3923 R4274 = R: RES CHIP 4.7K 1/16W +-5% (0402); CLASS: DISCRETE; MATERIAL: CHIP; Manuf_PN: RR0510S-472-JN; Manuf_name: CYNTEC CO.. LTD.; Manuftr: CYN; Part_Type: *LF_Resistor; TOLERANCE: 5%; WATTAGE: 1/16W
R3921 R3939-R3986 = R: RES CHIP 22 1/16W +-1%(0402); CLASS: DISCRETE; MATERIAL: CHIP; Manuf_PN: CR0222R0F002S; Manuf_name: RTECH TECHNOLOGY CO..LTD. (Compostar); Manuftr: RHT; Part_Type: *LF_Resistor; TOLERANCE: 1%; WATTAGE: 1/16W
C1161 C1163-C1170 C1180-C1185 C1189 C1191-C1201 C1218-C1221 PC110 PC117 PC215 PC317 PC615 = CAP_NP: CAP CHIP 100NF 50V(+-10%,X7R,0402); CLASS: DISCRETE; MATERIAL: X7R; Manuf_PN: CC0402KRX7R9BB104; Manuf_name: YAGEO CORPORATION; Manuftr: YGO; Part_Type: *LF_C0402; TOLERANCE: 10%; VOLTAGE: 50V
C1171 = CAP_NP: CAP CHIP 10U 16V(+-20%,X6S,0603); CLASS: DISCRETE; MATERIAL: X6S; Manuf_PN: GRM188C81C106M; Manuf_name: MURATA ERIE N.A. INC TAIWAN BRANCH Okayama Murata Mfg.Co..Ltd. Wakura Murata Mfg; Manuftr: MUR; Not_insert: NI; Part_Type: *LF_C0603; TOLERANCE: 20%; VOLTAGE: 16V
D18 = DIODE: DIODE SMD SDMK0340L-7-F(40V.30MA); CLASS: IC; MATERIAL: IC; Manuf_name: DIODES TAIWAN CO..LTD.(Kai Hong Shanghai); Manuftr: DDS; Part_Type: *LF_Semiconductor
J58 = SCONN8_5022800871001: CONN SMD WAFER 8P 1R MS(P1.0,H4.3)_FOR F09; CLASS: IO; ESD_CDM: NA; ESD_HBM: NA; ESD_MM: NA; MATERIAL: IO; MSD: NA; Manuf_PN: 50228-00871-001; Manuf_name: ACES ELECTRONIC CO., LTD.; Manuftr: ACS; PIN_LENGTH_LONG_PIN: 0 MILS; PIN_LENGTH_SHORT_PIN: 0 MILS; Part_Type: *LF_Connector
PR106-PR108 PR203 PR308 PR603 R3913-R3915 R4226 R4230 = R: RES CHIP 10K 1/16W 5%(0402); CLASS: DISCRETE; MATERIAL: CHIP; Manuf_PN: RR0510S-103-JN; Manuf_name: CYNTEC CO.. LTD.; Manuftr: CYN; Part_Type: *LF_Resistor; TOLERANCE: 5%; WATTAGE: 1/16W
R3917-R3920 R3924-R3938 R3987-R3989 R4096 R4361 R4362 = R: RES CHIP 22 1/16W +-1%(0402); BOM: AST2300; CLASS: DISCRETE; MATERIAL: CHIP; Manuf_PN: CR0222R0F002S; Manuf_name: RTECH TECHNOLOGY CO..LTD. (Compostar); Manufacturer: CYN; Manuftr: RHT; Part_Type: *LF_Resistor; TOLERANCE: 1%; WATTAGE: 1/16W
TP63 TP64 = TP: TEST POINT (TP26D10) DIP(DRILL10MILS); ALT_SYMBOLS: TOP:TP26D10;BOTTOM:TP30D10; CLASS: IO; DIP_SMD: DIP; MATERIAL: MISC; Not_insert: NI; Part_Type: Misc
U94 = LCMXO21200UHC4FTG256C: IC OTHER(256P)LCMXO2-1200UHC-4FTG2(FTBGA; CLASS: IC; MATERIAL: IC; Manuf_name: LATTICE SEMICONDUCTOR CORP.,; Manuftr: LSC; Part_Type: *LF_Chipset
C1160 C1162 = CAP_NP: CAP CHIP 1UF 25V(+-10%,X6S,0402); CLASS: DISCRETE; MATERIAL: X6S; Manuf_PN: GRM155C81E105K; Manuf_name: MURATA ERIE N.A. INC TAIWAN BRANCH Okayama Murata Mfg.Co..Ltd.Wakura Murata Mfg.; Manuftr: MUR; Part_Type: *LF_C0402; TOLERANCE: 10%; VOLTAGE: 25V
Q44 Q46-Q48 = MOSFET_PCH_GDS: TRANS MOS DMG3415U-7(-20V,-4A,0.9W)SOT23; CLASS: IC; MATERIAL: IC; Manuf_name: DIODES TAIWAN CO.,LTD.(Kai Hong Shanghai); Manuftr: DDS; Part_Type: *LF_Semiconductor
Q45 Q49 = MOSFET_NCH_GATE_PRO_DIODE_GDS: TRANS MOSFET DMN601WK-7(60V,300MA)SOT323; CLASS: IC; MATERIAL: IC; Manuf_name: DIODES TAIWAN CO.,LTD.(Kai Hong Shanghai); Manuftr: DDS; Part_Type: *LF_Semiconductor
PR103 PR104 PR303 PR304 R4218 R4231 = R: RES CHIP 10K 1/16W 5%(0402); CLASS: DISCRETE; MATERIAL: CHIP; Manuf_PN: RR0510S-103-JN; Manuf_name: CYNTEC CO.. LTD.; Manuftr: CYN; Not_insert: NI; Part_Type: *LF_Resistor; TOLERANCE: 5%; WATTAGE: 1/16W
R4219 R4227 = R: RESISTOR CHIP 0 1/10W+-5%(0603); CLASS: DISCRETE; MATERIAL: CHIP; Manuf_PN: CRCW06030000Z0EA; Manuf_name: DALE ELECTRONICS.INC.; Manuftr: DAL; Not_insert: NI; Part_Type: *LF_Resistor; TOLERANCE: 5%; WATTAGE: 1/10W
R4220-R4225 = R: RES CHIP 100K 1/16W +-1% (0402); CLASS: DISCRETE; MATERIAL: CHIP; Manuf_PN: RR0510S-104-FN; Manuf_name: CYNTEC CO.. LTD.; Manuftr: CYN; Part_Type: *LF_Resistor; TOLERANCE: 1%; WATTAGE: 1/16W
R4077-R4088 = R: RES CHIP 47 1/16W +-1% (0402)EF; CLASS: DISCRETE; FPLIST: R0402,R0402-0201; MATERIAL: CHIP; Manuf_PN: WR04X47R0FTR; Manuf_name: WALSIN TECHNOLOGY CORPORATION; Manuftr: WTC; Part_Type: *LF_Resistor; TOLERANCE: 1%; WATTAGE: 1/16W
U95-U100 = SN74LVC2G32DCUR: IC(8P) SN74LVC2G32DCUR(VSSOP-DCU); CLASS: IC; MATERIAL: IC; Manuf_name: TEXAS INSTRUMENTS SUPPLY CO.,; Manuftr: TIC; Part_Type: *LF_Chipset
PC101 PC118 PC216 PC301 = CAPACITOR_POL: CAP OSCON SMD 270U 16V(20%,105C,6.3*9.9); CLASS: DISCRETE; MATERIAL: ALUM; Manuf_PN: 16SVPG270M; Manuf_name: SANYO ELECTRIC CO., LTD.SANYO DENKI CO.,LTD; Manufacturer: NPN; Manuftr: SAY; Part_Type: *LF_C_ELEC_SMD; TOLERANCE: 20%; VOLTAGE: 16V
PC102-PC104 PC201-PC203 PC302 PC304 PC322 PC601-PC603 = CAP_NP: CAP CHIP 10U 25V(+-10%,X6S,0805)MUR; CLASS: DISCRETE; MATERIAL: X6S; Manuf_PN: GRM21BC81E106K; Manuf_name: MURATA ERIE N.A. INC TAIWAN BRANCH Okayama Murata Mfg.Co.,Ltd.Wakura Murata Mfg.; Manuftr: MUR; Part_Type: *LF_C0805; TOLERANCE: 10%; VOLTAGE: 25V
PC105 PC107 PC204 PC206 PC305 PC307 PC604 PC606 = CAP_NP: CAP CHIP 1UF 25V(+-10%,X6S,0402); CLASS: DISCRETE; FPLIST: C0402,C0402-0201; MATERIAL: X6S; Manuf_PN: GRM155C81E105K; Manuf_name: MURATA ERIE N.A. INC TAIWAN BRANCH Okayama Murata Mfg.Co..Ltd.Wakura Murata Mfg.; Manuftr: MUR; Part_Type: *LF_C0402; TOLERANCE: 10%; VOLTAGE: 25V
PC106 PC205 PC306 PC605 = CAP_NP: CAP CHIP 4.7UF 6.3V(+-20%,X6S,0402); CLASS: DISCRETE; FPLIST: C0402,C0402-0201; MATERIAL: X6S; Manuf_PN: GRM155C80J475M; Manuf_name: MURATA ERIE N.A. INC TAIWAN BRANCH Okayama Murata Mfg.Co.,; Manuftr: MUR; Part_Type: *LF_C0402; TOLERANCE: 20%; VOLTAGE: 6.3V
PC108 PC207 PC308 PC607 = CAP_NP: CAP CHIP 0.47UF 10V(+-10%,X7R,0402); CLASS: DISCRETE; MATERIAL: X7R; Manuf_PN: CC0402KRX7R6BB474; Manuf_name: YAGEO CORPORATION; Manuftr: YGO; Part_Type: *LF_C0402; TOLERANCE: 10%; VOLTAGE: 10V
PC109 = CAP_NP: CAP CHIP 150P 50V(+-5%.NPO.0402); CLASS: DISCRETE; MATERIAL: NPO; Manuf_PN: 0402N151J500LT; Manuf_name: WALSIN TECHNOLOGY CORPORATION; Manuftr: WTC; Part_Type: *LF_C0402; TOLERANCE: 5%; VOLTAGE: 50V
PC112 PC113 PC210 PC211 PC610 PC611 = CAP_NP: CAP CHIP 22U 6.3V(+-20%,X6S,0805)SAM; CLASS: DISCRETE; MATERIAL: X6S; Manuf_PN: CL21X226MQQNNNE; Manuf_name: SAMSUNG ELECTRONICS CO.,LTD (Samsung Mobile Display)SAMSUNG SDI CO.,LTD; Manuftr: SAM; Part_Type: *LF_C0805; TOLERANCE: 20%; VOLTAGE: 6.3V
PC114 PC119 PC212 PC612 = CAPACITOR_POL: CAP OSCON 220U 6.3V(20%,105C,5*5.8)SMD; CLASS: DISCRETE; MATERIAL: OSCON; Manuf_PN: APXF6R3ARA221ME611; Manuf_name: NIPPON CHEMI-CON; Manuftr: NPN; Part_Type: *LF_C_ELEC_SMD; SIDE: TOP; TOLERANCE: 20%; VOLTAGE: 6.3V
PC115 PC116 PC213 PC214 = CAPACITOR_POL: CAP 330U 6.3V(+-20%,ESR25M,7343,H=1.9); CLASS: DISCRETE; MATERIAL: POSCAP; Manuf_PN: 6TPE330MAP; Manuf_name: SANYO ELECTRIC CO., LTD.SANYO DENKI CO.,LTD; Manuftr: SAY; Part_Type: *LF_C_POSCAP; SIDE: TOP; TOLERANCE: 20%; VOLTAGE: 6.3V
PC120 = CAP_NP: CAP CHIP 1000P 50V(+-5%.X7R.0402); CLASS: DISCRETE; MATERIAL: X7R; Manuf_PN: C1005X7R102JGT; Manuf_name: ACER PERIPHERALS INC.(Darfon Electronics Corp.); Manuftr: API; Part_Type: *LF_C0402; TOLERANCE: 5%; VOLTAGE: 50V
PL101 PL201 PL601 = L: IND SMD 400NH 10% 40A(HCUVD8095D-401QL); CLASS: DISCRETE; Current_Amp: 40A; ESD_CDM: NA; ESD_HBM: NA; ESD_MM: NA; MATERIAL: IND; MSD: NA; Manuf_PN: HCUVD8095D-401QL; Manuf_name: DELTA ELECTRONIC IND. CO., LTD. DELTA ELECTRONICS; Manuftr: DTA; PIN_LENGTH_LONG_PIN: 0 MILS; PIN_LENGTH_SHORT_PIN: 0 MILS; Part_Type: *LF_Inductor
PL102 = L: IND SMD 80NH 20% 50A(HCBS5265-800); CLASS: DISCRETE; Current_Amp: 50A; MATERIAL: IND; Manuf_PN: HCBS5265-800; Manuf_name: DELTA ELECTRONIC IND. CO., LTD. DELTA ELECTRONICS COMPONENT(WUJIANG)LTD; Manuftr: DTA; Part_Type: *LF_Inductor; SIDE: TOP
PR101 PR201 PR301 PR601 = R: RES CHIP 60.4K 1/16W +-1%(0402); CLASS: DISCRETE; MATERIAL: CHIP; Manuf_PN: CR0260K4F002S; Manuf_name: RTECH TECHNOLOGY CO..LTD.(Compostar); Manuftr: RHT; Part_Type: *LF_Resistor; TOLERANCE: 1%; WATTAGE: 1/16W
PR105 PR202 PR602 = R: RES CHIP 15K 1/16W +-1% (0402); CLASS: DISCRETE; MATERIAL: CHIP; Manuf_PN: WR04X1502FTL; Manuf_name: WALSIN TECHNOLOGY CORPORATION; Manuftr: WTC; Part_Type: *LF_Resistor; TOLERANCE: 1%; WATTAGE: 1/16W
PR109 PR204 PR205 PR309 PR604 PR605 = R: RES CHIP 2.2 1/16W +-5%  (0402); CLASS: DISCRETE; MATERIAL: CHIP; Manuf_PN: RR0510S-2R2-JN; Manuf_name: CYNTEC CO.. LTD.; Manuftr: CYN; Part_Type: *LF_Resistor; TOLERANCE: 5%; WATTAGE: 1/16W
PR120 PR207 = R: RESISTOR CHIP 56K 1/16W +-1%(0402); CLASS: DISCRETE; MATERIAL: CHIP; Manuf_PN: CR0256K0F002S; Manuf_name: RTECH TECHNOLOGY CO..LTD.(Compostar); Manuftr: RHT; Part_Type: *LF_Resistor; TOLERANCE: 1%; WATTAGE: 1/16W
PR121 PR208 = R: RES CHIP 12.4K 1/16W +-1% (0402); CLASS: DISCRETE; MATERIAL: CHIP; Manuf_PN: CR0212K4F002S; Manuf_name: RTECH TECHNOLOGY CO..LTD.(Compostar); Manuftr: RHT; Part_Type: *LF_Resistor; TOLERANCE: 1%; WATTAGE: 1/16W
PR122 = R: RES CHIP 10K 1/16W +-1% (0402); CLASS: DISCRETE; MATERIAL: CHIP; Manuf_PN: RR0510S-103-FN; Manuf_name: CYNTEC CO.. LTD.; Manuftr: CYN; Part_Type: *LF_Resistor; TOLERANCE: 1%; WATTAGE: 1/16W
PR123 = R: RES CHIP 30.1K 1/16W +-1%(0402); CLASS: DISCRETE; MATERIAL: CHIP; Manuf_PN: RR0510S-3012-FN; Manuf_name: CYNTEC CO.. LTD.; Manuftr: CYN; Part_Type: *LF_Resistor; TOLERANCE: 1%; WATTAGE: 1/16W
PR124 PR126 PR128 PR206 PR606 = R: RESISTOR CHIP 0 1/16W +-5%(0402); CLASS: DISCRETE; MATERIAL: CHIP; Manuf_PN: RR0510X-000-XN; Manuf_name: CYNTEC CO.. LTD.; Manuftr: CYN; Part_Type: *LF_Resistor; TOLERANCE: 5%; WATTAGE: 1/16W
PR125 PR127 = R: RESISTOR CHIP 0 1/16W +-5%(0402); CLASS: DISCRETE; MATERIAL: CHIP; Manuf_PN: RR0510X-000-XN; Manuf_name: CYNTEC CO.. LTD.; Manuftr: CYN; Not_insert: NI; Part_Type: *LF_Resistor; TOLERANCE: 5%; WATTAGE: 1/16W
PU101 PU201 PU601 = MPQ8645PGVT6001Z: IC CTRL(25P)MPQ8645PGVT-6001-Z(TQFN); CLASS: IC; ESD_CDM: NA; ESD_HBM: NA; ESD_MM: NA; MATERIAL: IC; MSD: NA; Manuf_name: Monolithic Power Systems, Inc; Manuftr: MPS; PIN_LENGTH_LONG_PIN: 0 MILS; PIN_LENGTH_SHORT_PIN: 0 MILS; Part_Type: *LF_Chipset
TP65-TP67 = TP: TEST POINT (TP30T) SMD; ALT_SYMBOLS: TOP:TP30;BOTTOM:TP26; CLASS: IO; MATERIAL: MISC; Not_insert: NI; Part_Type: Misc
PC309 = CAP_NP: CAP CHIP 0.01U 50V(+-10%,X7R,0402); CLASS: DISCRETE; FPLIST: C0402,C0402-0201; MATERIAL: X7R; Manuf_PN: WBM155R71H103K; Manuf_name: MURATA ERIE N.A. INC TAIWAN BRANCH Okayama Murata Mfg.Co.,Ltd.; Manuftr: MUR; Part_Type: *LF_C0402; TOLERANCE: 10%; VOLTAGE: 50V
PC310 = CAP_NP: CAP CHIP 10P 50V(+-2%.NPO.0402); CLASS: DISCRETE; MATERIAL: NPO; Manuf_PN: 2238 869 14109; Manuf_name: PHYCOMP TAIWAN LTD.(YAGEO); Manuftr: PHY; Part_Type: *LF_C0402; TOLERANCE: 2%; VOLTAGE: 50V
PC311-PC315 = CAP_NP: CAP CHIP 47U 4V(+-20%,X6S,0805)MUR; CLASS: DISCRETE; MATERIAL: X6S; Manuf_PN: GRM21BC80G476M; Manuf_name: MURATA ERIE N.A. INC TAIWAN BRANCH Okayama Murata Mfg.Co.,Ltd.Wakura Murata Mfg.; Manuftr: MUR; Part_Type: *LF_C0805; TOLERANCE: 20%; VOLTAGE: 4V
PC316 PC318-PC321 = CAPACITOR_POL: CAP CHIP 470U 2V(+-20% ESR=3.7343)H1.9; CLASS: DISCRETE; MATERIAL: POSCAP; Manuf_PN: EEFGX0D471R; Manuf_name: MATSUSHITA ELECTRONICS CORPORATION (PANASONIC)Wuxi Matsushita Battery Co.. Ltd; Manuftr: MAT; Part_Type: *LF_C_POSCAP; SIDE: TOP; TOLERANCE: 20%; VOLTAGE: 2V
PJ1 = JUMPER-2_1: JUMP.SHORT_R0603; CLASS: IO; MATERIAL: MECH; Part_Type: Mech
PL301 = L: IND SMD 120NH 10% 94A(HCUVE966490D-121); CLASS: DISCRETE; Current_Amp: 94A; MATERIAL: IND; Manuf_PN: HCUVE966490D-121; Manuf_name: DELTA ELECTRONIC IND. CO., LTD. DELTA ELECTRONICS COMPONENT(WUJIANG)LTD; Manuftr: DTA; Part_Type: *LF_Inductor
PR305 = R: RES CHIP 34.8K 1/16W +-1% (0402)EP; CLASS: DISCRETE; MATERIAL: CHIP; Manuf_PN: WR04X3482FTL; Manuf_name: WALSIN TECHNOLOGY CORPORATION; Manuftr: WTC; Part_Type: *LF_Resistor; TOLERANCE: 1%; WATTAGE: 1/16W
PR306 = R: RES CHIP 3.3 1/16W +-1%(0402)EF; CLASS: DISCRETE; FPLIST: R0402,R0402-0201; MATERIAL: CHIP; Manuf_PN: RC0402FR-073R3P; Manuf_name: YAGEO CORPORATION; Manuftr: YGO; Part_Type: *LF_Resistor; TOLERANCE: 1%; WATTAGE: 1/16W
PR307 = R: RES CHIP 10K 1/16W 5%(0402); CLASS: DISCRETE; FPLIST: R0402,R0402-0201; MATERIAL: CHIP; Manuf_PN: RR0510S-103-JN; Manuf_name: CYNTEC CO.. LTD.; Manuftr: CYN; Part_Type: *LF_Resistor; TOLERANCE: 5%; WATTAGE: 1/16W
PR320 = R: RES CHIP  9.76K 1/16W  +-0.1%(0402); CLASS: DISCRETE; MATERIAL: CHIP; Manuf_PN: WF04U9761BTL; Manuf_name: WALSIN TECHNOLOGY CORPORATION; Manuftr: WTC; Part_Type: *LF_Resistor; TOLERANCE: 0.1%; WATTAGE: 1/16W
PR321 = R: RES CHIP 18.2K 1/16W +-0.1%(0402); CLASS: DISCRETE; MATERIAL: CHIP; Manuf_PN: WF04T1822BTL; Manuf_name: WALSIN TECHNOLOGY CORPORATION; Manuftr: WTC; Part_Type: *LF_Resistor; TOLERANCE: 0.1%; WATTAGE: 1/16W
PU301 = MPQ8645PGVTZ: IC CTRL(25P)MPQ8645PGVT-6000-Z(TQFN); CLASS: IC; ESD_CDM: NA; ESD_HBM: NA; ESD_MM: NA; MATERIAL: IC; MSD: NA; Manuf_name: Monolithic Power Systems, Inc; Manuftr: MPS; PIN_LENGTH_LONG_PIN: 0 MILS; PIN_LENGTH_SHORT_PIN: 0 MILS; Part_Type: *LF_Chipset

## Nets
GND: C1160.2 C1161.2 C1162.2 C1163.2 C1164.2 C1165.2 C1166.2 C1167.2 C1168.2 C1169.2 C1170.2 C1171.2 C1180.2 C1181.2 C1182.2 C1183.2 C1184.2 C1185.2 C1189.2 C1191.2 C1192.2 C1193.2 C1194.2 C1195.2 C1196.2 C1197.2 C1198.2 C1199.2 C1200.2 C1201.2 C1218.2 C1219.1 C1220.2 C1221.1 J58.7 J58.G1 J58.G2 PC101.2 PC102.2 PC103.2 PC104.2 PC105.2 PC106.2 PC107.2 PC110.2 PC112.2 PC113.2 PC114.2 PC115.2 PC116.2 PC117.2 PC118.2 PC119.2 PC201.2 PC202.2 PC203.2 PC204.2 PC205.2 PC206.2 PC210.2 PC211.2 PC212.2 PC213.2 PC214.2 PC215.2 PC216.2 PC301.2 PC302.2 PC304.2 PC305.2 PC306.2 PC307.2 PC310.2 PC311.2 PC312.2 PC313.2 PC314.2 PC315.2 PC316.2 PC317.2 PC318.2 PC319.2 PC320.2 PC321.2 PC322.2 PC601.2 PC602.2 PC603.2 PC604.2 PC605.2 PC606.2 PC610.2 PC611.2 PC612.2 PC615.2 PR101.1 PR105.1 PR122.1 PR127.1 PR128.1 PR201.1 PR202.1 PR208.1 PR301.1 PR305.1 PR321.1 PR601.1 PR602.1 PU101.4(PGND1) PU101.14(PGND2) PU101.15(PGND3) PU101.23(AGND) PU201.4(PGND1) PU201.14(PGND2) PU201.15(PGND3) PU201.21(VOSNS-) PU201.23(AGND) PU301.4(PGND1) PU301.14(PGND2) PU301.15(PGND3) PU301.17(PS#) PU301.21(VOSNS-) PU301.23(AGND) PU601.4(PGND1) PU601.14(PGND2) PU601.15(PGND3) PU601.21(VOSNS-) PU601.23(AGND) Q45.S Q49.S R3916.2 R4218.1 R4226.1 TP66.1 U94.B2(GND0) U94.B15(GND1) U94.C3(GND2) U94.C14(GND3) U94.D4(GND4) U94.D13(GND5) U94.E5(GND6) U94.E12(GND7) U94.F6(GND8) U94.F11(GND9) U94.H8(GND10) U94.H9(GND11) U94.J8(GND12) U94.J9(GND13) U94.L6(GND14) U94.L11(GND15) U94.M5(GND16) U94.M12(GND17) U94.N4(GND18) U94.N13(GND19) U94.P3(GND20) U94.P14(GND21) U94.R2(GND22) U94.R15(GND23) U95.4(GND) U96.4(GND) U97.4(GND) U98.4(GND) U99.4(GND) U100.4(GND) ; also on sheet 12 13 17 18 19 20 21 22 23 24 25 26 27 28 29 30 31 32 33 34 35 36 37 38 39 40 41 42 43 44 45 46 47 48 49 50 58 61 62 63 64 65 66 67
P0V9_ADDR1: PR305.2 PU301.18(ADDR)
P0V9_BOOTC: PC308.1 PR306.1
P0V9_CTRL: PU301.9(CTRL) ; also on sheet 12
P0V9_IREF1: PR301.2 PU301.20(IREF)
P0V9_TAKE1: PR308.2 PU301.11(PASS) PU301.12(TAKE)
P0V9_VCC: PC306.1 PR307.1 PR308.1 PU301.24(VCC)
P0V9_VDRV1: PC307.1 PR303.2 PR304.2 PR309.2 PU301.5(VDRV)
P0V9_VOSNS+: PC309.1 PR320.1 PR321.2 PU301.22(VOSNS+)
P0V92: PC311.1 PC312.1 PC313.1 PC314.1 PC315.1 PC316.1 PC318.1 PC319.1 PC320.1 PC321.1 PJ1.2 PL301.2 ; also on sheet 50 64 65
P0V92_SENSE+: PC309.2 PC310.1 PJ1.1 PR320.2
P1V8: C1219.2 Q46.D R4219.1 ; also on sheet 17 18 19 22 23 24 25 26 27 28 29 30 31 32 33 34 35 36 37 44 49 50 58 62 65 67
P3V3_BOOTC_1: PC108.1 PR124.1
P3V3_BOOTC_2: PC207.1 PR206.1
P3V3_BOOTC_3: PC607.1 PR606.1
P3V3_M2A_EN: U95.1(1A) ; also on sheet 38 46
P3V3_M2B_EN: U95.5(2A) ; also on sheet 38 46
P3V3_M2C_EN: U96.1(1A) ; also on sheet 38 46
P3V3_M2D_EN: U96.5(2A) ; also on sheet 38 46
P3V3_M2E_EN: U97.1(1A) ; also on sheet 38 46
P3V3_M2F_EN: U97.5(2A) ; also on sheet 38 46
P3V3_M2G_EN: U98.1(1A) ; also on sheet 38 46
P3V3_M2H_EN: U98.5(2A) ; also on sheet 38 46
P3V3_M2I_EN: U99.1(1A) ; also on sheet 38 46
P3V3_M2J_EN: U99.5(2A) ; also on sheet 38 46
P3V3_M2K_EN: U100.1(1A) ; also on sheet 38 46
P3V3_M2L_EN: U100.5(2A) ; also on sheet 38 46
P3V3_OR_M2A_EN: R4077.2 ; also on sheet 39
P3V3_OR_M2A_EN_R: R4077.1 U95.7(1Y)
P3V3_OR_M2B_EN: R4078.2 ; also on sheet 39
P3V3_OR_M2B_EN_R: R4078.1 U95.3(2Y)
P3V3_OR_M2C_EN: R4079.2 ; also on sheet 39
P3V3_OR_M2C_EN_R: R4079.1 U96.7(1Y)
P3V3_OR_M2D_EN: R4080.2 ; also on sheet 39
P3V3_OR_M2D_EN_R: R4080.1 U96.3(2Y)
P3V3_OR_M2E_EN: R4081.2 ; also on sheet 40
P3V3_OR_M2E_EN_R: R4081.1 U97.7(1Y)
P3V3_OR_M2F_EN: R4082.2 ; also on sheet 40
P3V3_OR_M2F_EN_R: R4082.1 U97.3(2Y)
P3V3_OR_M2G_EN: R4083.2 ; also on sheet 40
P3V3_OR_M2G_EN_R: R4083.1 U98.7(1Y)
P3V3_OR_M2H_EN: R4084.2 ; also on sheet 40
P3V3_OR_M2H_EN_R: R4084.1 U98.3(2Y)
P3V3_OR_M2I_EN: R4085.2 ; also on sheet 41
P3V3_OR_M2I_EN_R: R4085.1 U99.7(1Y)
P3V3_OR_M2J_EN: R4086.2 ; also on sheet 41
P3V3_OR_M2J_EN_R: R4086.1 U99.3(2Y)
P3V3_OR_M2K_EN: R4087.2 ; also on sheet 41
P3V3_OR_M2K_EN_R: R4087.1 U100.7(1Y)
P3V3_OR_M2L_EN: R4088.2 ; also on sheet 41
P3V3_OR_M2L_EN_R: R4088.1 U100.3(2Y)
P3V3_STBY: C1160.1 C1161.1 C1162.1 C1163.1 C1164.1 C1165.1 C1166.1 C1167.1 C1168.1 C1169.1 C1180.1 C1181.1 C1182.1 C1183.1 C1184.1 C1185.1 C1221.2 D18.1 PC110.1 PC112.1 PC113.1 PC114.1 PC115.1 PC116.1 PC119.1 PC210.1 PC211.1 PC212.1 PC213.1 PC214.1 PC610.1 PC611.1 PC612.1 PL101.2 PL201.2 PL601.2 PR125.1 PR126.1 PR207.2 PR309.1 Q47.D R3913.1 R3914.1 R3915.1 R3923.2 R4227.1 R4230.2 R4231.2 R4274.2 U94.A1(VCC0) U94.A16(VCC1) U94.D5(VCCIO0_3) U94.D12(VCCIO0_1) U94.G7(VCC4) U94.G8(VCCIO0_0) U94.G9(VCCIO0_2) U94.G10(VCC5) U94.K7(VCC6) U94.K10(VCC7) U94.T1(VCC2) U94.T16(VCC3) U95.8(VCC) U96.8(VCC) U97.8(VCC) U98.8(VCC) U99.8(VCC) U100.8(VCC) ; also on sheet 12 17 18 19 20 22 23 24 25 26 27 28 29 30 31 32 33 34 35 36 37 38 39 40 41 42 43 44 45 46 47 48 49 50 58 61 67
P3V3_STBY_ADDR1: PR105.2 PU101.18(ADDR)
P3V3_STBY_ADDR2: PR202.2 PU201.18(ADDR)
P3V3_STBY_ADDR3: PR602.2 PU601.18(ADDR)
P3V3_STBY_CPLD_JTAG: C1170.1 C1171.1 D18.2 J58.1
P3V3_STBY_CTRL: PR122.2 PR123.2 PU101.9(CTRL) PU201.9(CTRL) PU601.9(CTRL)
P3V3_STBY_IREF1: PR101.2 PU101.20(IREF)
P3V3_STBY_IREF2: PR201.2 PU201.20(IREF)
P3V3_STBY_IREF3: PR601.2 PU601.20(IREF)
P3V3_STBY_ISUM1: PU101.19(ISUM) PU201.19(ISUM) PU601.19(ISUM)
P3V3_STBY_PS#1: PR106.2 PU101.17(PS#)
P3V3_STBY_PS#2: PR203.2 PU201.17(PS#)
P3V3_STBY_PS#3: PR603.2 PU601.17(PS#)
P3V3_STBY_SET: PU101.13(SET) PU201.13(SET) PU601.13(SET)
P3V3_STBY_TAKE1: PR108.2 PU101.12(TAKE) PU601.11(PASS)
P3V3_STBY_TAKE2: PU101.11(PASS) PU201.12(TAKE)
P3V3_STBY_TAKE3: PU201.11(PASS) PU601.12(TAKE)
P3V3_STBY_VCC: PC106.1 PC205.1 PC605.1 PR106.1 PR107.1 PR108.1 PR109.2 PR203.1 PR204.2 PR603.1 PR604.2 PU101.24(VCC) PU201.24(VCC) PU601.24(VCC)
P3V3_STBY_VDRV1: PC107.1 PR103.2 PR104.2 PR109.1 PR205.2 PR605.2 PU101.5(VDRV)
P3V3_STBY_VDRV2: PC206.1 PR204.1 PR205.1 PU201.5(VDRV)
P3V3_STBY_VDRV3: PC606.1 PR604.1 PR605.1 PU601.5(VDRV)
P3V3_STBY_VOSNS2+: PR207.1 PR208.2 PU201.22(VOSNS+) PU601.22(VOSNS+)
P3V3_STBY_VOSNS+: PC109.1 PR120.1 PR121.2 PU101.22(VOSNS+)
P3V3_STBY_VOSNS-: PC120.2 PR121.1 PR127.2 PR128.2 PU101.21(VOSNS-)
P12V_STBY: PL102.1 PR123.1 ; also on sheet 42 50 61
VCCIO_PLD_1_5: C1189.1 C1191.1 C1192.1 C1193.1 C1194.1 C1195.1 C1196.1 C1197.1 C1198.1 C1199.1 C1200.1 C1201.1 C1218.1 C1220.1 Q44.D Q48.D R3922.2 R4219.2 R4227.2 U94.E4(VCCIO5) U94.E13(VCCIO1_0) U94.H7(VCCIO4_1) U94.H10(VCCIO1_1) U94.J7(VCCIO4_0) U94.J10(VCCIO1_2) U94.K8(VCCIO2_2) U94.K9(VCCIO2_0) U94.M4(VCCIO3) U94.M13(VCCIO1_3) U94.N5(VCCIO2_3) U94.N12(VCCIO2_1)
VCCIO_PMOS_1_S: Q44.S Q46.S R4220.1
VCCIO_PMOS_2_S: Q47.S Q48.S R4223.1
COM_CPLD_M2A_RX: R3924.1 ; also on sheet 24
COM_CPLD_M2A_RX_R: R3924.2 U94.H14(PR7A|PCLKT1_0)
COM_CPLD_M2A_TX: U94.E16(PR3A) ; also on sheet 24
COM_CPLD_M2B_RX: R3925.1 ; also on sheet 25
COM_CPLD_M2B_RX_R: R3925.2 U94.H16(PR7B|PCLKC1_0)
COM_CPLD_M2B_TX: U94.F15(PR3B) ; also on sheet 25
COM_CPLD_M2C_RX: R3926.1 ; also on sheet 26
COM_CPLD_M2C_RX_R: R3926.2 U94.J16(PR7C)
COM_CPLD_M2C_TX: U94.F13(PR3C) ; also on sheet 26
COM_CPLD_M2D_RX: R3927.1 ; also on sheet 27
COM_CPLD_M2D_RX_R: R3927.2 U94.J14(PR7D)
COM_CPLD_M2D_TX: U94.G12(PR3D) ; also on sheet 27
COM_CPLD_M2E_RX: R3928.1 ; also on sheet 28
COM_CPLD_M2E_RX_R: R3928.2 U94.J15(PR9A)
COM_CPLD_M2E_TX: U94.F14(PR4A) ; also on sheet 28
COM_CPLD_M2F_RX: R3929.1 ; also on sheet 29
COM_CPLD_M2F_RX_R: R3929.2 U94.K16(PR9B)
COM_CPLD_M2F_TX: U94.F16(PR4B) ; also on sheet 29
COM_CPLD_M2G_RX: R3930.1 ; also on sheet 30
COM_CPLD_M2G_RX_R: R3930.2 U94.H11(PR9C)
COM_CPLD_M2G_TX: U94.F12(PR4C) ; also on sheet 30
COM_CPLD_M2H_RX: R3931.1 ; also on sheet 31
COM_CPLD_M2H_RX_R: R3931.2 U94.J13(PR9D)
COM_CPLD_M2H_TX: U94.G13(PR4D) ; also on sheet 31
COM_CPLD_M2I_RX: R3932.1 ; also on sheet 32
COM_CPLD_M2I_RX_R: R3932.2 U94.K14(PR10A)
COM_CPLD_M2I_TX: U94.G15(PR5A) ; also on sheet 32
COM_CPLD_M2J_RX: R3933.1 ; also on sheet 33
COM_CPLD_M2J_RX_R: R3933.2 U94.K15(PR10B)
COM_CPLD_M2J_TX: U94.G14(PR5B) ; also on sheet 33
COM_CPLD_M2K_RX: R3934.1 ; also on sheet 34
COM_CPLD_M2K_RX_R: R3934.2 U94.J11(PR10C)
COM_CPLD_M2K_TX: U94.G11(PR5C) ; also on sheet 34
COM_CPLD_M2L_RX: R3935.1 ; also on sheet 35
COM_CPLD_M2L_RX_R: R3935.2 U94.L12(PR10D)
COM_CPLD_M2L_TX: U94.H12(PR5D) ; also on sheet 35
COM_GP_RX: U94.B6(PT11B) ; also on sheet 12
COM_GP_TX: R3936.2 ; also on sheet 12
COM_GP_TX_R: R3936.1 U94.A5(PT11A)
FM_BIC_M2A_EN: U95.2(1B) ; also on sheet 47
FM_BIC_M2B_EN: U95.6(2B) ; also on sheet 47
FM_BIC_M2C_EN: U96.2(1B) ; also on sheet 47
FM_BIC_M2D_EN: U96.6(2B) ; also on sheet 47
FM_BIC_M2E_EN: U97.2(1B) ; also on sheet 47
FM_BIC_M2F_EN: U97.6(2B) ; also on sheet 47
FM_BIC_M2G_EN: U98.2(1B) ; also on sheet 47
FM_BIC_M2H_EN: U98.6(2B) ; also on sheet 47
FM_BIC_M2I_EN: U99.2(1B) ; also on sheet 47
FM_BIC_M2J_EN: U99.6(2B) ; also on sheet 47
FM_BIC_M2K_EN: U100.2(1B) ; also on sheet 47
FM_BIC_M2L_EN: U100.6(2B) ; also on sheet 47
FM_COM_EN_N: U94.C12(PT23A) ; also on sheet 47
FM_COM_SEL_0: U94.B12(PT23B) ; also on sheet 47
FM_COM_SEL_1: U94.B14(PT24A) ; also on sheet 47
FM_COM_SEL_2: U94.A15(PT24B) ; also on sheet 47
FM_COM_SEL_3: U94.A13(PT24C|INITN) ; also on sheet 47
FM_JTAG_EN_N: U94.A11(PT21A) ; also on sheet 47
FM_JTAG_SEL_0: U94.C11(PT21B) ; also on sheet 47
FM_JTAG_SEL_1: U94.F10(PT21C) ; also on sheet 47
FM_JTAG_SEL_2: U94.D11(PT21D) ; also on sheet 47
FM_JTAG_SEL_3: U94.B11(PT22A) ; also on sheet 47
FM_PLD_VCCIO_1_5_P1V8: R4218.2 R4222.2 R4230.1 ; also on sheet 47
FM_PLD_VCCIO_1_5_P3V3SB: R4225.2 R4226.2 R4231.1 ; also on sheet 47
FM_PLD_VCCIO_PMOS_1_G: Q44.G Q46.G R4220.2 R4221.1
FM_PLD_VCCIO_PMOS_2_G: Q47.G Q48.G R4223.2 R4224.1
FM_PLD_VCCIO_Q45_D: Q45.D R4221.2
FM_PLD_VCCIO_Q45_G: Q45.G R4222.1
FM_PLD_VCCIO_Q49_D: Q49.D R4224.2
FM_PLD_VCCIO_Q49_G: Q49.G R4225.1
JTAG_BIC_M2_TCK: U94.C5(PT10B) ; also on sheet 46
JTAG_BIC_M2_TDI: U94.C4(PT9A) ; also on sheet 46
JTAG_BIC_M2_TDO: R3938.2 ; also on sheet 46
JTAG_BIC_M2_TDO_R: R3938.1 U94.B5(PT9B)
JTAG_BIC_M2_TMS: U94.B3(PT9C) ; also on sheet 46
JTAG_BIC_M2_TRST: U94.A4(PT10A) ; also on sheet 46
JTAG_CPLD_M2A_TCK: R3975.2 ; also on sheet 24
JTAG_CPLD_M2A_TCK_R: R3975.1 U94.R8(PB11B|PCLKC2_0)
JTAG_CPLD_M2A_TDI: R3939.1 ; also on sheet 24
JTAG_CPLD_M2A_TDI_R: R3939.2 U94.D1(PL1B|L_GPLLC_FB)
JTAG_CPLD_M2A_TDO: U94.G3(PL5B) ; also on sheet 24
JTAG_CPLD_M2A_TMS: R3951.1 ; also on sheet 24
JTAG_CPLD_M2A_TMS_R: R3951.2 U94.K2(PL10B)
JTAG_CPLD_M2A_TRST: R3963.2 ; also on sheet 24
JTAG_CPLD_M2A_TRST_R: R3963.1 U94.T4(PB3B)
JTAG_CPLD_M2B_TCK: R3976.2 ; also on sheet 25
JTAG_CPLD_M2B_TCK_R: R3976.1 U94.M6(PB11C)
JTAG_CPLD_M2B_TDI: R3940.1 ; also on sheet 25
JTAG_CPLD_M2B_TDI_R: R3940.2 U94.B1(PL1C)
JTAG_CPLD_M2B_TDO: U94.F5(PL5C) ; also on sheet 25
JTAG_CPLD_M2B_TMS: R3952.1 ; also on sheet 25
JTAG_CPLD_M2B_TMS_R: R3952.2 U94.J5(PL10C)
JTAG_CPLD_M2B_TRST: R3964.2 ; also on sheet 25
JTAG_CPLD_M2B_TRST_R: R3964.1 U94.T2(PB3C)
JTAG_CPLD_M2C_TCK: R3977.2 ; also on sheet 26
JTAG_CPLD_M2C_TCK_R: R3977.1 U94.L8(PB11D)
JTAG_CPLD_M2C_TDI: R3941.1 ; also on sheet 26
JTAG_CPLD_M2C_TDI_R: R3941.2 U94.C2(PL1D)
JTAG_CPLD_M2C_TDO: U94.H6(PL5D) ; also on sheet 26
JTAG_CPLD_M2C_TMS: R3953.1 ; also on sheet 26
JTAG_CPLD_M2C_TMS_R: R3953.2 U94.K6(PL10D)
JTAG_CPLD_M2C_TRST: R3965.2 ; also on sheet 26
JTAG_CPLD_M2C_TRST_R: R3965.1 U94.R3(PB3D)
JTAG_CPLD_M2D_TCK: R3978.2 ; also on sheet 27
JTAG_CPLD_M2D_TCK_R: R3978.1 U94.P8(PB12A)
JTAG_CPLD_M2D_TDI: R3942.1 ; also on sheet 27
JTAG_CPLD_M2D_TDI_R: R3942.2 U94.E2(PL2A|L_GPLLT_IN)
JTAG_CPLD_M2D_TDO: U94.G1(PL6A) ; also on sheet 27
JTAG_CPLD_M2D_TMS: R3954.1 ; also on sheet 27
JTAG_CPLD_M2D_TMS_R: R3954.2 U94.L1(PL11A)
JTAG_CPLD_M2D_TRST: R3966.2 ; also on sheet 27
JTAG_CPLD_M2D_TRST_R: R3966.1 U94.R5(PB5A|CSSPIN)
JTAG_CPLD_M2E_TCK: R3979.2 ; also on sheet 28
JTAG_CPLD_M2E_TCK_R: R3979.1 U94.T8(PB12B)
JTAG_CPLD_M2E_TDI: R3943.1 ; also on sheet 28
JTAG_CPLD_M2E_TDI_R: R3943.2 U94.E3(PL2B|L_GPLLC_IN)
JTAG_CPLD_M2E_TDO: U94.H2(PL6B) ; also on sheet 28
JTAG_CPLD_M2E_TMS: R3955.1 ; also on sheet 28
JTAG_CPLD_M2E_TMS_R: R3955.2 U94.L3(PL11B)
JTAG_CPLD_M2E_TRST: R3967.2 ; also on sheet 28
JTAG_CPLD_M2E_TRST_R: R3967.1 U94.P5(PB5B)
JTAG_CPLD_M2F_TCK: R3980.2 ; also on sheet 29
JTAG_CPLD_M2F_TCK_R: R3980.1 U94.N8(PB12C)
JTAG_CPLD_M2F_TDI: R3944.1 ; also on sheet 29
JTAG_CPLD_M2F_TDI_R: R3944.2 U94.C1(PL2C)
JTAG_CPLD_M2F_TDO: U94.H4(PL6C) ; also on sheet 29
JTAG_CPLD_M2F_TMS: R3956.1 ; also on sheet 29
JTAG_CPLD_M2F_TMS_R: R3956.2 U94.K4(PL11C)
JTAG_CPLD_M2F_TRST: R3968.2 ; also on sheet 29
JTAG_CPLD_M2F_TRST_R: R3968.1 U94.T5(PB6A)
JTAG_CPLD_M2G_TCK: R3981.2 ; also on sheet 30
JTAG_CPLD_M2G_TCK_R: R3981.1 U94.L9(PB12D)
JTAG_CPLD_M2G_TDI: R3945.1 ; also on sheet 30
JTAG_CPLD_M2G_TDI_R: R3945.2 U94.D2(PL2D)
JTAG_CPLD_M2G_TDO: U94.J6(PL6D) ; also on sheet 30
JTAG_CPLD_M2G_TMS: R3957.1 ; also on sheet 30
JTAG_CPLD_M2G_TMS_R: R3957.2 U94.L5(PL11D)
JTAG_CPLD_M2G_TRST: R3969.2 ; also on sheet 30
JTAG_CPLD_M2G_TRST_R: R3969.1 U94.R6(PB6B)
JTAG_CPLD_M2H_TCK: R3982.2 ; also on sheet 31
JTAG_CPLD_M2H_TCK_R: R3982.1 U94.T9(PB16A|PCLKT2_1)
JTAG_CPLD_M2H_TDI: R3946.1 ; also on sheet 31
JTAG_CPLD_M2H_TDI_R: R3946.2 U94.E1(PL3A|PCLKT5_0)
JTAG_CPLD_M2H_TDO: U94.H3(PL7A) ; also on sheet 31
JTAG_CPLD_M2H_TMS: R3958.1 ; also on sheet 31
JTAG_CPLD_M2H_TMS_R: R3958.2 U94.L2(PL12A|PCLKT3_0)
JTAG_CPLD_M2H_TRST: R3970.2 ; also on sheet 31
JTAG_CPLD_M2H_TRST_R: R3970.1 U94.T3(PB6C)
JTAG_CPLD_M2I_TCK: R3983.2 ; also on sheet 32
JTAG_CPLD_M2I_TCK_R: R3983.1 U94.P9(PB16B|PCLKC2_1)
JTAG_CPLD_M2I_TDI: R3947.1 ; also on sheet 32
JTAG_CPLD_M2I_TDI_R: R3947.2 U94.F2(PL3B|PCLKC5_0)
JTAG_CPLD_M2I_TDO: U94.H1(PL7B) ; also on sheet 32
JTAG_CPLD_M2I_TMS: R3959.1 ; also on sheet 32
JTAG_CPLD_M2I_TMS_R: R3959.2 U94.M1(PL12B|PCLKC3_0)
JTAG_CPLD_M2I_TRST: R3971.2 ; also on sheet 32
JTAG_CPLD_M2I_TRST_R: R3971.1 U94.R4(PB6D)
JTAG_CPLD_M2J_TCK: R3984.2 ; also on sheet 33
JTAG_CPLD_M2J_TCK_R: R3984.1 U94.M8(PB16C)
JTAG_CPLD_M2J_TDI: R3948.1 ; also on sheet 33
JTAG_CPLD_M2J_TDI_R: R3948.2 U94.F4(PL3C)
JTAG_CPLD_M2J_TDO: U94.J1(PL7C|PCLKT4_0) ; also on sheet 33
JTAG_CPLD_M2J_TMS: R3960.1 ; also on sheet 33
JTAG_CPLD_M2J_TMS_R: R3960.2 U94.K5(PL12C)
JTAG_CPLD_M2J_TRST: R3972.2 ; also on sheet 33
JTAG_CPLD_M2J_TRST_R: R3972.1 U94.P6(PB8A|MCLK_CCLK)
JTAG_CPLD_M2K_TCK: R3985.2 ; also on sheet 34
JTAG_CPLD_M2K_TCK_R: R3985.1 U94.N9(PB16D)
JTAG_CPLD_M2K_TDI: R3949.1 ; also on sheet 34
JTAG_CPLD_M2K_TDI_R: R3949.2 U94.G6(PL3D)
JTAG_CPLD_M2K_TDO: U94.J3(PL7D|PCLKC4_0) ; also on sheet 34
JTAG_CPLD_M2K_TMS: R3961.1 ; also on sheet 34
JTAG_CPLD_M2K_TMS_R: R3961.2 U94.L4(PL12D)
JTAG_CPLD_M2K_TRST: R3973.2 ; also on sheet 34
JTAG_CPLD_M2K_TRST_R: R3973.1 U94.T6(PB8B|SO_SPISO)
JTAG_CPLD_M2L_TCK: R3986.2 ; also on sheet 35
JTAG_CPLD_M2L_TCK_R: R3986.1 U94.R9(PB18A)
JTAG_CPLD_M2L_TDI: R3950.1 ; also on sheet 35
JTAG_CPLD_M2L_TDI_R: R3950.2 U94.F3(PL4A)
JTAG_CPLD_M2L_TDO: U94.J2(PL9A) ; also on sheet 35
JTAG_CPLD_M2L_TMS: R3962.1 ; also on sheet 35
JTAG_CPLD_M2L_TMS_R: R3962.2 U94.M3(PL13A)
JTAG_CPLD_M2L_TRST: R3974.2 ; also on sheet 35
JTAG_CPLD_M2L_TRST_R: R3974.1 U94.N6(PB8C)
JTAG_CPLD_TCK: J58.8 R3916.1 R3920.2
JTAG_CPLD_TCK_R: R3920.1 U94.A7(PT16C|TCK)
JTAG_CPLD_TDI: J58.3 R3913.2 R3918.2
JTAG_CPLD_TDI_R: R3918.1 U94.A6(PT12D|TDI)
JTAG_CPLD_TDO: J58.2 R3915.2 R3917.2
JTAG_CPLD_TDO_R: R3917.1 U94.C6(PT12C|TDO)
JTAG_CPLD_TMS: J58.6 R3914.2 R3919.2
JTAG_CPLD_TMS_R: R3919.1 U94.B8(PT16D|TMS)
PU_CPLD_JTAGENB: R4274.1 U94.C10(PT20C|JTAGENB)
PU_CPLD_PROGRAMN: R3923.1 U94.B10(PT20D|PROGRAMN)
PU_CPLD_SN: R3922.1 U94.R12(PB25A|SN)
PWRGD_P0V92: PR307.2 PU301.10(PG) ; also on sheet 67
PWRGD_P3V3_STBY: PR107.2 PU101.10(PG) PU201.10(PG) PU601.10(PG) ; also on sheet 12
SMB_BIC_CPLD_0_CLK: R3989.2 ; also on sheet 61
SMB_BIC_CPLD_0_CLK_R1: R3989.1 U94.F8(PT18A)
SMB_BIC_CPLD_0_DAT: R3988.2 ; also on sheet 61
SMB_BIC_CPLD_0_DAT_R1: R3988.1 U94.D9(PT18B)
SMB_BIC_CPLD_1_CLK: R3987.2 ; also on sheet 61
SMB_BIC_CPLD_1_CLK_R1: R3987.1 U94.A9(PT18C|SCL_PCLKT0_0)
SMB_BIC_CPLD_1_DAT: R3921.2 ; also on sheet 61
SMB_BIC_CPLD_1_DAT_R1: R3921.1 U94.C9(PT18D|SDA_PCLKC0_0)
SMB_MUX_VR_CLK: PR104.1 PR304.1 PU101.6(SCL) PU201.6(SCL) PU301.6(SCL) PU601.6(SCL) TP65.1 ; also on sheet 61
SMB_MUX_VR_DAT: PR103.1 PR303.1 PU101.7(SDA) PU201.7(SDA) PU301.7(SDA) PU601.7(SDA) TP67.1 ; also on sheet 61
SW_P0V9_1: PC308.2 PL301.1 PU301.2(SW1) PU301.3(SW2)
SW_P0V9_BT_1: PR306.2 PU301.25(BST)
SW_P3V3_STBY_1: PC108.2 PL101.1 PU101.2(SW1) PU101.3(SW2)
SW_P3V3_STBY_2: PC207.2 PL201.1 PU201.2(SW1) PU201.3(SW2)
SW_P3V3_STBY_3: PC607.2 PL601.1 PU601.2(SW1) PU601.3(SW2)
SW_P3V3_STBY_BT_1: PR124.2 PU101.25(BST)
SW_P3V3_STBY_BT_2: PR206.2 PU201.25(BST)
SW_P3V3_STBY_BT_3: PR606.2 PU601.25(BST)
SW_P12V_FLT: PC101.1 PC102.1 PC103.1 PC104.1 PC105.1 PC117.1 PC118.1 PC201.1 PC202.1 PC203.1 PC204.1 PC215.1 PC216.1 PC301.1 PC302.1 PC304.1 PC305.1 PC317.1 PC322.1 PC601.1 PC602.1 PC603.1 PC604.1 PC615.1 PL102.2 PU101.1(IN1) PU101.16(IN2) PU201.1(IN1) PU201.16(IN2) PU301.1(IN1) PU301.16(IN2) PU601.1(IN1) PU601.16(IN2)
TP_JTAG_CONN_5: J58.5 TP64.1
TP_JTAG_PCH_LAN_TRST_N: J58.4 TP63.1
UART_BIC_RXD: R3937.2 ; also on sheet 46
UART_BIC_RXD_R: R3937.1 U94.C7(PT13B)
UART_BIC_RXD_REMOTE: R4096.2 ; also on sheet 46
UART_BIC_RXD_REMOTE_R: R4096.1 U94.D7(PT13D)
UART_BIC_TXD: U94.B7(PT13A) ; also on sheet 46
UART_BIC_TXD_REMOTE: U94.E6(PT13C) ; also on sheet 46
UART_PESW_CPLD_USIN: R4362.2 ; also on sheet 18
UART_PESW_CPLD_USIN_R: R4362.1 U94.A8(PT17B|PCLKC0_1)
UART_PESW_CPLD_USOUT: R4361.2 ; also on sheet 18
UART_PESW_CPLD_USOUT_R: R4361.1 U94.C8(PT17A|PCLKT0_1)
N13628460: PC109.2 PC120.1 PR120.2 PR125.2 PR126.2

Not connected (* = marked no-connect by the designer): PU101 8(ALT#)*; PU201 8(ALT#)*; PU301 8(ALT#)* 13(SET)* 19(ISUM)*; PU601 8(ALT#)*; U94 A2(NC1)* A3(PT11C) A10(PT19B) A12(PT22B) A14(PT22D) B4(PT11D) B9(PT19A) B13(PT22C) B16(PR1D) C13(PT24D|DONE) C15(PR1C) C16(PR2C) D3(PL1A|L_GPLLT_FB) D6(PT12A) D8(PT17C) D10(PT20A) D14(PR1A) D15(PR2D) D16(PR2A) E7(PT12B) E8(PT16B) E9(PT17D) E10(PT20B) E11(PT19D) E14(PR2B) E15(PR1B) F1(PL4B) F7(PT16A) F9(PT19C) G2(PL5A) G4(PL4D) G5(PL4C) G16(PR6A) H5(PL9C) H13(PR6C) H15(PR6B) J4(PL9D) J12(PR6D) K1(PL9B) K3(PL10A) K11(PR12C) K12(PR11D) K13(PR11C) L7(PB8D) L10(PB18D) L13(PR12D) L14(PR11B) L15(PR12A) L16(PR11A) M2(PL14A) M7(PB9C) M9(PB18C) M10(PB21C) M11(PB19D) M14(PR13A) M15(PR13B) M16(PR12B) N1(PL13B) N2(PL13C) N3(PL14B) N7(PB9D) N10(PB19C) N11(PB21D) N14(PR14B) N15(PR13C) N16(PR14A) P1(PL13D) P2(PL14D) P4(PB3A) P7(PB9B) P10(PB19A) P11(PB21B) P12(PB24A) P13(PB25B|SI_SISPI) P15(PR14C) P16(PR13D) R1(PL14C) R7(PB9A) R10(PB19B) R11(PB22A) R13(PB22C) R14(PB25D) R16(PR14D) T7(PB11A|PCLKT2_0) T10(PB18B) T11(PB21A) T12(PB22B) T13(PB24B) T14(PB22D) T15(PB25C)

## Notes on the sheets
sheet 51
- CPLD 1
sheet 52
- BOM Note:
  J58 change to 50228-00801-001
- CPLD 2
sheet 53
- CPLD 3
sheet 54
- MISC 1
sheet 55
- MISC 2
sheet 56
- Design specification
- Output Voltage =3.3 V+/-5%
  Output Ripple & Noise :<100mVpp
  Transient Tolerance = 330mV
  Max current = 43A ; (43A-73A for 20uS)
  Over-Current Protection(Max Rating x1.2) = 87.6A
  Current Step =43-73A for 20uS, period time=1mS
  Slew Rate = 12A/us
  Work frequency =600KHZ
  Efficiency > 90%
- ISAT=40A@100C
  SIZE=5.2*5.2*6.5
- ESR=8m ohm
  6.3*9.9
- ESR=8m ohm
  6.3*9.9
- DCR=0.8mohm
  ISAT=40A@100C
  SIZE=8*8*9.5
- Note: Change from 3 pin header to
  SMD test point due to VR update
  and it causes space limitaton.
- Ra
- VEN>2.1V HIGH
  VEN<0.8V LOW
  4.3V MAX
- ADDR=31H
- Rb
- Vo=0.6(1+Ra/Rb) = 3.309V
- Layout Note: Vsense
  The net of PR126 to P3V3_STBY
  use differentail pair connect to C251
- cap size 5*5.8
- DCR=0.8mohm
  ISAT=40A@100C
  SIZE=8*8*9.5
- ESR=8m ohm
  6.3*9.9
- cap size 5*5.8
- ADDR=31H
- DCR=0.8mohm
  ISAT=40A@100C
  SIZE=8*8*9.5
- cap size 5*5.8
- ADDR=31H
- Note:
  Add PWRGD_P3v3_STBY off page.
- P3V3 STBY
sheet 57
- Design specification
- Output Voltage = 0.92V ∮2.5%
  Output Ripple & Noise: <46mVpp
  Transient Tolerance = 46mV
  Max current = 30.27A
  Over-Current Protection(Max Rating x 1.3) = 40A
  Current Step = 15.5A (50% ~ 100%)
  Slew Rate = 2.5A/US
  Work frequency = 400KHZ
  Efficiency>80%
  Update date: 2018/11/19
- DCR=0.17mohm
  ISAT=75A@125C
  SIZE=9.6*9*6.4
- Ra
- VEN>2.1V HIGH
  VEN<0.8V LOW
  4.3V MAX
- ADDR=33H
- Rb
- Layout Note:
  Place Short Pad PJ1
  close to U34 side.
- Vo=0.6(1+Ra/Rb) = 0.9217V
- PC320 in bottom ; PC321 closed to C590
- Note:
  Add PWRGD_P0V92 off page.
- P0V92
